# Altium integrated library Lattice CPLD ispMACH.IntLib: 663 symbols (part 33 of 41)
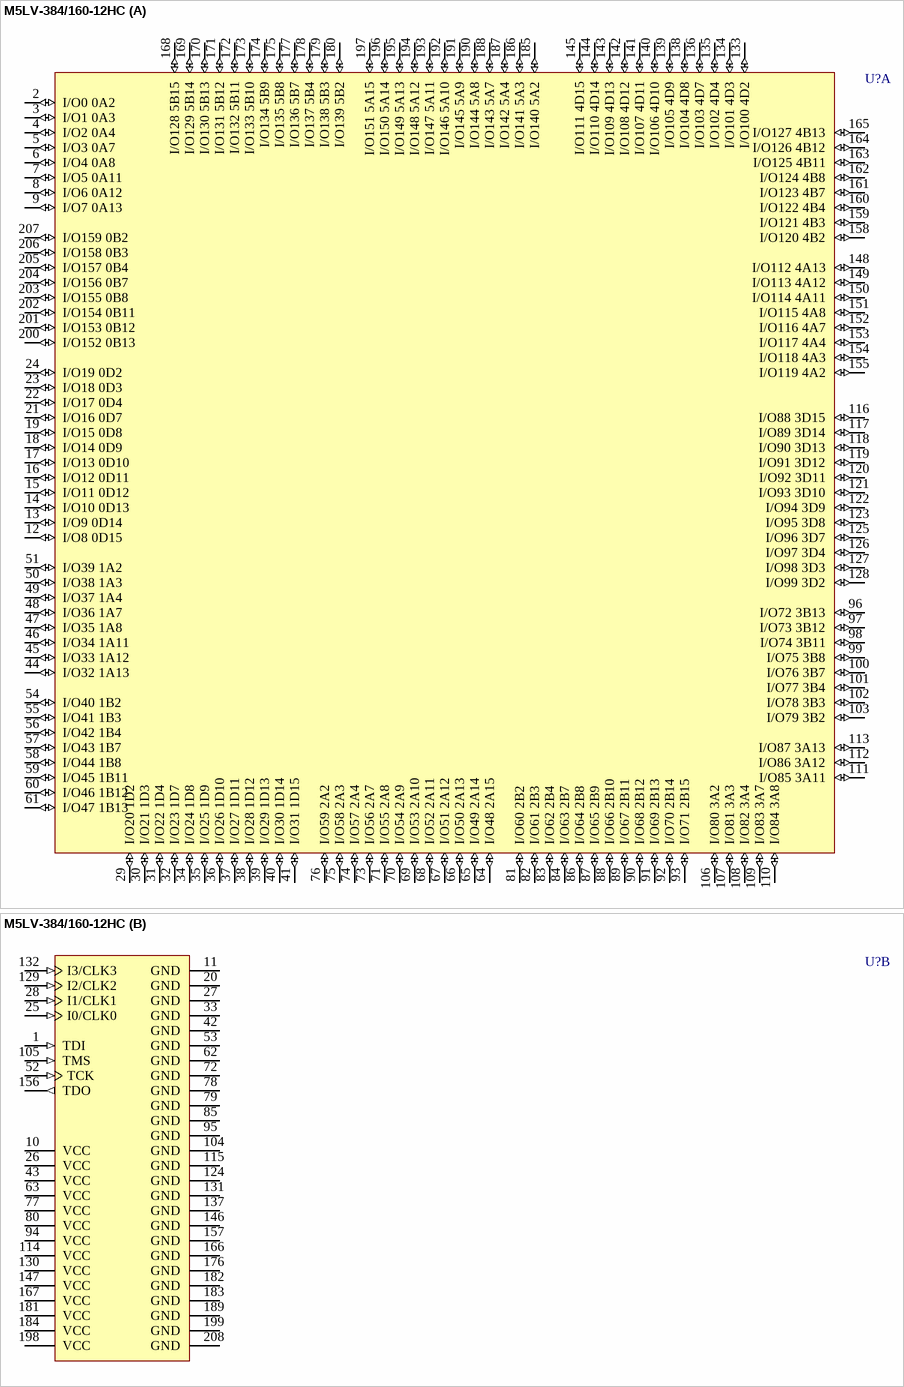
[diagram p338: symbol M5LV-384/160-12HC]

## M5LV-384/160-12HC
designator U?
High-Density and High-I/O Complex PLD
footprint MQFP208_N (Shrink QFP, 208-Leads, Body 27.7x27.7mm, Pitch 0.5mm, IPC Medium Density)
footprint MQFP208_L (Shrink QFP, 208-Leads, Body 27.7x27.7mm, Pitch 0.5mm, IPC High Density)
footprint MQFP208_M (Shrink QFP, 208-Leads, Body 27.7x27.7mm, Pitch 0.5mm, IPC Low Density)
3D model M5LV-MQFP208 (208-Pin Shrink Quad Flat Pack 0.5 mm Pitch)
part A pins: 2 I/O0 0A2 (io), 3 I/O1 0A3 (io), 4 I/O2 0A4 (io), 5 I/O3 0A7 (io), 6 I/O4 0A8 (io), 7 I/O5 0A11 (io), 8 I/O6 0A12 (io), 9 I/O7 0A13 (io), 12 I/O8 0D15 (io), 13 I/O9 0D14 (io), 14 I/O10 0D13 (io), 15 I/O11 0D12 (io), 16 I/O12 0D11 (io), 17 I/O13 0D10 (io), 18 I/O14 0D9 (io), 19 I/O15 0D8 (io), 21 I/O16 0D7 (io), 22 I/O17 0D4 (io), 23 I/O18 0D3 (io), 24 I/O19 0D2 (io), 29 I/O20 1D2 (io), 30 I/O21 1D3 (io), 31 I/O22 1D4 (io), 32 I/O23 1D7 (io), 34 I/O24 1D8 (io), 35 I/O25 1D9 (io), 36 I/O26 1D10 (io), 37 I/O27 1D11 (io), 38 I/O28 1D12 (io), 39 I/O29 1D13 (io), 40 I/O30 1D14 (io), 41 I/O31 1D15 (io), 44 I/O32 1A13 (io), 45 I/O33 1A12 (io), 46 I/O34 1A11 (io), 47 I/O35 1A8 (io), 48 I/O36 1A7 (io), 49 I/O37 1A4 (io), 50 I/O38 1A3 (io), 51 I/O39 1A2 (io), 54 I/O40 1B2 (io), 55 I/O41 1B3 (io), 56 I/O42 1B4 (io), 57 I/O43 1B7 (io), 58 I/O44 1B8 (io), 59 I/O45 1B11 (io), 60 I/O46 1B12 (io), 61 I/O47 1B13 (io), 64 I/O48 2A15 (io), 65 I/O49 2A14 (io), 66 I/O50 2A13 (io), 67 I/O51 2A12 (io), 68 I/O52 2A11 (io), 69 I/O53 2A10 (io), 70 I/O54 2A9 (io), 71 I/O55 2A8 (io), 73 I/O56 2A7 (io), 74 I/O57 2A4 (io), 75 I/O58 2A3 (io), 76 I/O59 2A2 (io), 81 I/O60 2B2 (io), 82 I/O61 2B3 (io), 83 I/O62 2B4 (io), 84 I/O63 2B7 (io), 86 I/O64 2B8 (io), 87 I/O65 2B9 (io), 88 I/O66 2B10 (io), 89 I/O67 2B11 (io), 90 I/O68 2B12 (io), 91 I/O69 2B13 (io), 92 I/O70 2B14 (io), 93 I/O71 2B15 (io), 96 I/O72 3B13 (io), 97 I/O73 3B12 (io), 98 I/O74 3B11 (io), 99 I/O75 3B8 (io), 100 I/O76 3B7 (io), 101 I/O77 3B4 (io), 102 I/O78 3B3 (io), 103 I/O79 3B2 (io), 106 I/O80 3A2 (io), 107 I/O81 3A3 (io), 108 I/O82 3A4 (io), 109 I/O83 3A7 (io), 110 I/O84 3A8 (io), 111 I/O85 3A11 (io), 112 I/O86 3A12 (io), 113 I/O87 3A13 (io), 116 I/O88 3D15 (io), 117 I/O89 3D14 (io), 118 I/O90 3D13 (io), 119 I/O91 3D12 (io), 120 I/O92 3D11 (io), 121 I/O93 3D10 (io), 122 I/O94 3D9 (io), 123 I/O95 3D8 (io), 125 I/O96 3D7 (io), 126 I/O97 3D4 (io), 127 I/O98 3D3 (io), 128 I/O99 3D2 (io), 133 I/O100 4D2 (io), 134 I/O101 4D3 (io), 135 I/O102 4D4 (io), 136 I/O103 4D7 (io), 138 I/O104 4D8 (io), 139 I/O105 4D9 (io), 140 I/O106 4D10 (io), 141 I/O107 4D11 (io), 142 I/O108 4D12 (io), 143 I/O109 4D13 (io), 144 I/O110 4D14 (io), 145 I/O111 4D15 (io), 148 I/O112 4A13 (io), 149 I/O113 4A12 (io), 150 I/O114 4A11 (io), 151 I/O115 4A8 (io), 152 I/O116 4A7 (io), 153 I/O117 4A4 (io), 154 I/O118 4A3 (io), 155 I/O119 4A2 (io), 158 I/O120 4B2 (io), 159 I/O121 4B3 (io), 160 I/O122 4B4 (io), 161 I/O123 4B7 (io), 162 I/O124 4B8 (io), 163 I/O125 4B11 (io), 164 I/O126 4B12 (io), 165 I/O127 4B13 (io), 168 I/O128 5B15 (io), 169 I/O129 5B14 (io), 170 I/O130 5B13 (io), 171 I/O131 5B12 (io), 172 I/O132 5B11 (io), 173 I/O133 5B10 (io), 174 I/O134 5B9 (io), 175 I/O135 5B8 (io), 177 I/O136 5B7 (io), 178 I/O137 5B4 (io), 179 I/O138 5B3 (io), 180 I/O139 5B2 (io), 185 I/O140 5A2 (io), 186 I/O141 5A3 (io), 187 I/O142 5A4 (io), 188 I/O143 5A7 (io), 190 I/O144 5A8 (io), 191 I/O145 5A9 (io), 192 I/O146 5A10 (io), 193 I/O147 5A11 (io), 194 I/O148 5A12 (io), 195 I/O149 5A13 (io), 196 I/O150 5A14 (io), 197 I/O151 5A15 (io), 200 I/O152 0B13 (io), 201 I/O153 0B12 (io), 202 I/O154 0B11 (io), 203 I/O155 0B8 (io), 204 I/O156 0B7 (io), 205 I/O157 0B4 (io), 206 I/O158 0B3 (io), 207 I/O159 0B2 (io)
part B pins: 1 TDI (in), 10 VCC (power), 11 GND (power), 20 GND (power), 25 I0/CLK0 (in), 26 VCC (power), 27 GND (power), 28 I1/CLK1 (in), 33 GND (power), 42 GND (power), 43 VCC (power), 52 TCK (in), 53 GND (power), 62 GND (power), 63 VCC (power), 72 GND (power), 77 VCC (power), 78 GND (power), 79 GND (power), 80 VCC (power), 85 GND (power), 94 VCC (power), 95 GND (power), 104 GND (power), 105 TMS (in), 114 VCC (power), 115 GND (power), 124 GND (power), 129 I2/CLK2 (in), 130 VCC (power), 131 GND (power), 132 I3/CLK3 (in), 137 GND (power), 146 GND (power), 147 VCC (power), 156 TDO (out), 157 GND (power), 166 GND (power), 167 VCC (power), 176 GND (power), 181 VCC (power), 182 GND (power), 183 GND (power), 184 VCC (power), 189 GND (power), 198 VCC (power), 199 GND (power), 208 GND (power)

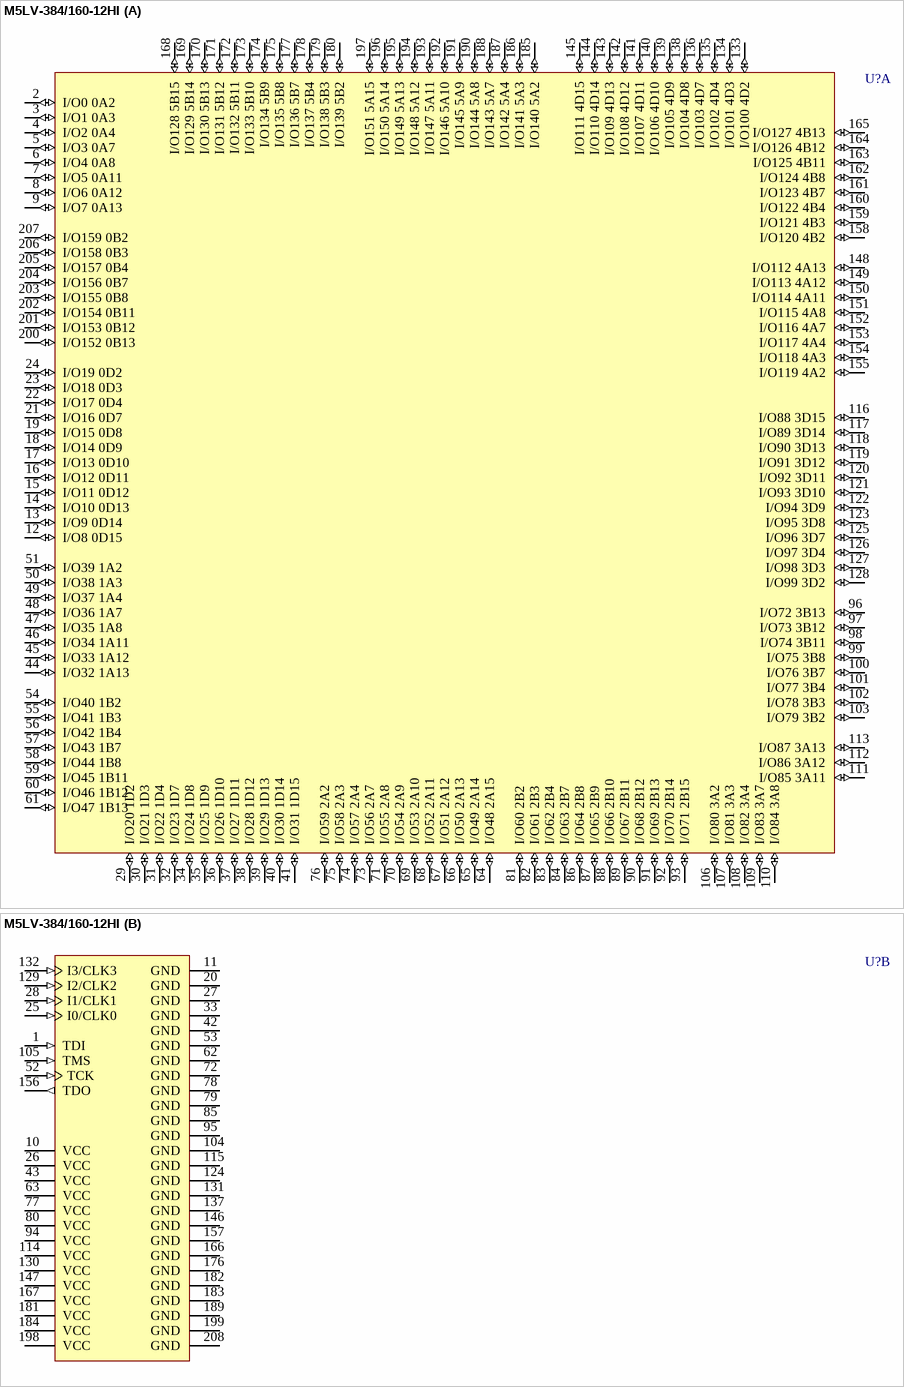
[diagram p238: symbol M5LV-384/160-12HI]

## M5LV-384/160-12HI
designator U?
High-Density and High-I/O Complex PLD
footprint MQFP208_N (Shrink QFP, 208-Leads, Body 27.7x27.7mm, Pitch 0.5mm, IPC Medium Density)
footprint MQFP208_L (Shrink QFP, 208-Leads, Body 27.7x27.7mm, Pitch 0.5mm, IPC High Density)
footprint MQFP208_M (Shrink QFP, 208-Leads, Body 27.7x27.7mm, Pitch 0.5mm, IPC Low Density)
3D model M5LV-MQFP208 (208-Pin Shrink Quad Flat Pack 0.5 mm Pitch)
part A pins: 2 I/O0 0A2 (io), 3 I/O1 0A3 (io), 4 I/O2 0A4 (io), 5 I/O3 0A7 (io), 6 I/O4 0A8 (io), 7 I/O5 0A11 (io), 8 I/O6 0A12 (io), 9 I/O7 0A13 (io), 12 I/O8 0D15 (io), 13 I/O9 0D14 (io), 14 I/O10 0D13 (io), 15 I/O11 0D12 (io), 16 I/O12 0D11 (io), 17 I/O13 0D10 (io), 18 I/O14 0D9 (io), 19 I/O15 0D8 (io), 21 I/O16 0D7 (io), 22 I/O17 0D4 (io), 23 I/O18 0D3 (io), 24 I/O19 0D2 (io), 29 I/O20 1D2 (io), 30 I/O21 1D3 (io), 31 I/O22 1D4 (io), 32 I/O23 1D7 (io), 34 I/O24 1D8 (io), 35 I/O25 1D9 (io), 36 I/O26 1D10 (io), 37 I/O27 1D11 (io), 38 I/O28 1D12 (io), 39 I/O29 1D13 (io), 40 I/O30 1D14 (io), 41 I/O31 1D15 (io), 44 I/O32 1A13 (io), 45 I/O33 1A12 (io), 46 I/O34 1A11 (io), 47 I/O35 1A8 (io), 48 I/O36 1A7 (io), 49 I/O37 1A4 (io), 50 I/O38 1A3 (io), 51 I/O39 1A2 (io), 54 I/O40 1B2 (io), 55 I/O41 1B3 (io), 56 I/O42 1B4 (io), 57 I/O43 1B7 (io), 58 I/O44 1B8 (io), 59 I/O45 1B11 (io), 60 I/O46 1B12 (io), 61 I/O47 1B13 (io), 64 I/O48 2A15 (io), 65 I/O49 2A14 (io), 66 I/O50 2A13 (io), 67 I/O51 2A12 (io), 68 I/O52 2A11 (io), 69 I/O53 2A10 (io), 70 I/O54 2A9 (io), 71 I/O55 2A8 (io), 73 I/O56 2A7 (io), 74 I/O57 2A4 (io), 75 I/O58 2A3 (io), 76 I/O59 2A2 (io), 81 I/O60 2B2 (io), 82 I/O61 2B3 (io), 83 I/O62 2B4 (io), 84 I/O63 2B7 (io), 86 I/O64 2B8 (io), 87 I/O65 2B9 (io), 88 I/O66 2B10 (io), 89 I/O67 2B11 (io), 90 I/O68 2B12 (io), 91 I/O69 2B13 (io), 92 I/O70 2B14 (io), 93 I/O71 2B15 (io), 96 I/O72 3B13 (io), 97 I/O73 3B12 (io), 98 I/O74 3B11 (io), 99 I/O75 3B8 (io), 100 I/O76 3B7 (io), 101 I/O77 3B4 (io), 102 I/O78 3B3 (io), 103 I/O79 3B2 (io), 106 I/O80 3A2 (io), 107 I/O81 3A3 (io), 108 I/O82 3A4 (io), 109 I/O83 3A7 (io), 110 I/O84 3A8 (io), 111 I/O85 3A11 (io), 112 I/O86 3A12 (io), 113 I/O87 3A13 (io), 116 I/O88 3D15 (io), 117 I/O89 3D14 (io), 118 I/O90 3D13 (io), 119 I/O91 3D12 (io), 120 I/O92 3D11 (io), 121 I/O93 3D10 (io), 122 I/O94 3D9 (io), 123 I/O95 3D8 (io), 125 I/O96 3D7 (io), 126 I/O97 3D4 (io), 127 I/O98 3D3 (io), 128 I/O99 3D2 (io), 133 I/O100 4D2 (io), 134 I/O101 4D3 (io), 135 I/O102 4D4 (io), 136 I/O103 4D7 (io), 138 I/O104 4D8 (io), 139 I/O105 4D9 (io), 140 I/O106 4D10 (io), 141 I/O107 4D11 (io), 142 I/O108 4D12 (io), 143 I/O109 4D13 (io), 144 I/O110 4D14 (io), 145 I/O111 4D15 (io), 148 I/O112 4A13 (io), 149 I/O113 4A12 (io), 150 I/O114 4A11 (io), 151 I/O115 4A8 (io), 152 I/O116 4A7 (io), 153 I/O117 4A4 (io), 154 I/O118 4A3 (io), 155 I/O119 4A2 (io), 158 I/O120 4B2 (io), 159 I/O121 4B3 (io), 160 I/O122 4B4 (io), 161 I/O123 4B7 (io), 162 I/O124 4B8 (io), 163 I/O125 4B11 (io), 164 I/O126 4B12 (io), 165 I/O127 4B13 (io), 168 I/O128 5B15 (io), 169 I/O129 5B14 (io), 170 I/O130 5B13 (io), 171 I/O131 5B12 (io), 172 I/O132 5B11 (io), 173 I/O133 5B10 (io), 174 I/O134 5B9 (io), 175 I/O135 5B8 (io), 177 I/O136 5B7 (io), 178 I/O137 5B4 (io), 179 I/O138 5B3 (io), 180 I/O139 5B2 (io), 185 I/O140 5A2 (io), 186 I/O141 5A3 (io), 187 I/O142 5A4 (io), 188 I/O143 5A7 (io), 190 I/O144 5A8 (io), 191 I/O145 5A9 (io), 192 I/O146 5A10 (io), 193 I/O147 5A11 (io), 194 I/O148 5A12 (io), 195 I/O149 5A13 (io), 196 I/O150 5A14 (io), 197 I/O151 5A15 (io), 200 I/O152 0B13 (io), 201 I/O153 0B12 (io), 202 I/O154 0B11 (io), 203 I/O155 0B8 (io), 204 I/O156 0B7 (io), 205 I/O157 0B4 (io), 206 I/O158 0B3 (io), 207 I/O159 0B2 (io)
part B pins: 1 TDI (in), 10 VCC (power), 11 GND (power), 20 GND (power), 25 I0/CLK0 (in), 26 VCC (power), 27 GND (power), 28 I1/CLK1 (in), 33 GND (power), 42 GND (power), 43 VCC (power), 52 TCK (in), 53 GND (power), 62 GND (power), 63 VCC (power), 72 GND (power), 77 VCC (power), 78 GND (power), 79 GND (power), 80 VCC (power), 85 GND (power), 94 VCC (power), 95 GND (power), 104 GND (power), 105 TMS (in), 114 VCC (power), 115 GND (power), 124 GND (power), 129 I2/CLK2 (in), 130 VCC (power), 131 GND (power), 132 I3/CLK3 (in), 137 GND (power), 146 GND (power), 147 VCC (power), 156 TDO (out), 157 GND (power), 166 GND (power), 167 VCC (power), 176 GND (power), 181 VCC (power), 182 GND (power), 183 GND (power), 184 VCC (power), 189 GND (power), 198 VCC (power), 199 GND (power), 208 GND (power)

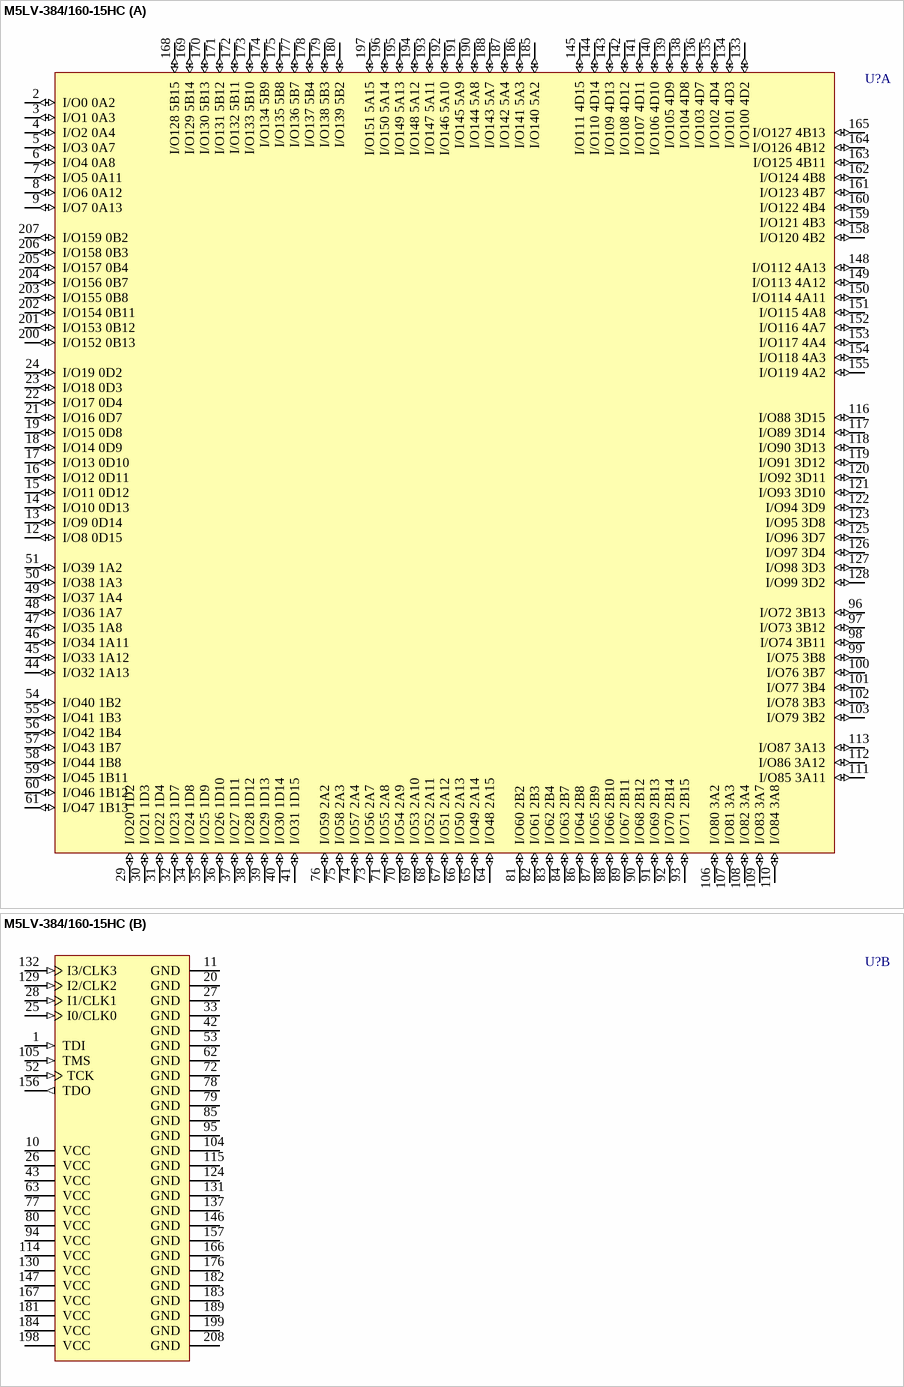
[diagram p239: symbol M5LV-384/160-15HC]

## M5LV-384/160-15HC
designator U?
High-Density and High-I/O Complex PLD
footprint MQFP208_N (Shrink QFP, 208-Leads, Body 27.7x27.7mm, Pitch 0.5mm, IPC Medium Density)
footprint MQFP208_L (Shrink QFP, 208-Leads, Body 27.7x27.7mm, Pitch 0.5mm, IPC High Density)
footprint MQFP208_M (Shrink QFP, 208-Leads, Body 27.7x27.7mm, Pitch 0.5mm, IPC Low Density)
3D model M5LV-MQFP208 (208-Pin Shrink Quad Flat Pack 0.5 mm Pitch)
part A pins: 2 I/O0 0A2 (io), 3 I/O1 0A3 (io), 4 I/O2 0A4 (io), 5 I/O3 0A7 (io), 6 I/O4 0A8 (io), 7 I/O5 0A11 (io), 8 I/O6 0A12 (io), 9 I/O7 0A13 (io), 12 I/O8 0D15 (io), 13 I/O9 0D14 (io), 14 I/O10 0D13 (io), 15 I/O11 0D12 (io), 16 I/O12 0D11 (io), 17 I/O13 0D10 (io), 18 I/O14 0D9 (io), 19 I/O15 0D8 (io), 21 I/O16 0D7 (io), 22 I/O17 0D4 (io), 23 I/O18 0D3 (io), 24 I/O19 0D2 (io), 29 I/O20 1D2 (io), 30 I/O21 1D3 (io), 31 I/O22 1D4 (io), 32 I/O23 1D7 (io), 34 I/O24 1D8 (io), 35 I/O25 1D9 (io), 36 I/O26 1D10 (io), 37 I/O27 1D11 (io), 38 I/O28 1D12 (io), 39 I/O29 1D13 (io), 40 I/O30 1D14 (io), 41 I/O31 1D15 (io), 44 I/O32 1A13 (io), 45 I/O33 1A12 (io), 46 I/O34 1A11 (io), 47 I/O35 1A8 (io), 48 I/O36 1A7 (io), 49 I/O37 1A4 (io), 50 I/O38 1A3 (io), 51 I/O39 1A2 (io), 54 I/O40 1B2 (io), 55 I/O41 1B3 (io), 56 I/O42 1B4 (io), 57 I/O43 1B7 (io), 58 I/O44 1B8 (io), 59 I/O45 1B11 (io), 60 I/O46 1B12 (io), 61 I/O47 1B13 (io), 64 I/O48 2A15 (io), 65 I/O49 2A14 (io), 66 I/O50 2A13 (io), 67 I/O51 2A12 (io), 68 I/O52 2A11 (io), 69 I/O53 2A10 (io), 70 I/O54 2A9 (io), 71 I/O55 2A8 (io), 73 I/O56 2A7 (io), 74 I/O57 2A4 (io), 75 I/O58 2A3 (io), 76 I/O59 2A2 (io), 81 I/O60 2B2 (io), 82 I/O61 2B3 (io), 83 I/O62 2B4 (io), 84 I/O63 2B7 (io), 86 I/O64 2B8 (io), 87 I/O65 2B9 (io), 88 I/O66 2B10 (io), 89 I/O67 2B11 (io), 90 I/O68 2B12 (io), 91 I/O69 2B13 (io), 92 I/O70 2B14 (io), 93 I/O71 2B15 (io), 96 I/O72 3B13 (io), 97 I/O73 3B12 (io), 98 I/O74 3B11 (io), 99 I/O75 3B8 (io), 100 I/O76 3B7 (io), 101 I/O77 3B4 (io), 102 I/O78 3B3 (io), 103 I/O79 3B2 (io), 106 I/O80 3A2 (io), 107 I/O81 3A3 (io), 108 I/O82 3A4 (io), 109 I/O83 3A7 (io), 110 I/O84 3A8 (io), 111 I/O85 3A11 (io), 112 I/O86 3A12 (io), 113 I/O87 3A13 (io), 116 I/O88 3D15 (io), 117 I/O89 3D14 (io), 118 I/O90 3D13 (io), 119 I/O91 3D12 (io), 120 I/O92 3D11 (io), 121 I/O93 3D10 (io), 122 I/O94 3D9 (io), 123 I/O95 3D8 (io), 125 I/O96 3D7 (io), 126 I/O97 3D4 (io), 127 I/O98 3D3 (io), 128 I/O99 3D2 (io), 133 I/O100 4D2 (io), 134 I/O101 4D3 (io), 135 I/O102 4D4 (io), 136 I/O103 4D7 (io), 138 I/O104 4D8 (io), 139 I/O105 4D9 (io), 140 I/O106 4D10 (io), 141 I/O107 4D11 (io), 142 I/O108 4D12 (io), 143 I/O109 4D13 (io), 144 I/O110 4D14 (io), 145 I/O111 4D15 (io), 148 I/O112 4A13 (io), 149 I/O113 4A12 (io), 150 I/O114 4A11 (io), 151 I/O115 4A8 (io), 152 I/O116 4A7 (io), 153 I/O117 4A4 (io), 154 I/O118 4A3 (io), 155 I/O119 4A2 (io), 158 I/O120 4B2 (io), 159 I/O121 4B3 (io), 160 I/O122 4B4 (io), 161 I/O123 4B7 (io), 162 I/O124 4B8 (io), 163 I/O125 4B11 (io), 164 I/O126 4B12 (io), 165 I/O127 4B13 (io), 168 I/O128 5B15 (io), 169 I/O129 5B14 (io), 170 I/O130 5B13 (io), 171 I/O131 5B12 (io), 172 I/O132 5B11 (io), 173 I/O133 5B10 (io), 174 I/O134 5B9 (io), 175 I/O135 5B8 (io), 177 I/O136 5B7 (io), 178 I/O137 5B4 (io), 179 I/O138 5B3 (io), 180 I/O139 5B2 (io), 185 I/O140 5A2 (io), 186 I/O141 5A3 (io), 187 I/O142 5A4 (io), 188 I/O143 5A7 (io), 190 I/O144 5A8 (io), 191 I/O145 5A9 (io), 192 I/O146 5A10 (io), 193 I/O147 5A11 (io), 194 I/O148 5A12 (io), 195 I/O149 5A13 (io), 196 I/O150 5A14 (io), 197 I/O151 5A15 (io), 200 I/O152 0B13 (io), 201 I/O153 0B12 (io), 202 I/O154 0B11 (io), 203 I/O155 0B8 (io), 204 I/O156 0B7 (io), 205 I/O157 0B4 (io), 206 I/O158 0B3 (io), 207 I/O159 0B2 (io)
part B pins: 1 TDI (in), 10 VCC (power), 11 GND (power), 20 GND (power), 25 I0/CLK0 (in), 26 VCC (power), 27 GND (power), 28 I1/CLK1 (in), 33 GND (power), 42 GND (power), 43 VCC (power), 52 TCK (in), 53 GND (power), 62 GND (power), 63 VCC (power), 72 GND (power), 77 VCC (power), 78 GND (power), 79 GND (power), 80 VCC (power), 85 GND (power), 94 VCC (power), 95 GND (power), 104 GND (power), 105 TMS (in), 114 VCC (power), 115 GND (power), 124 GND (power), 129 I2/CLK2 (in), 130 VCC (power), 131 GND (power), 132 I3/CLK3 (in), 137 GND (power), 146 GND (power), 147 VCC (power), 156 TDO (out), 157 GND (power), 166 GND (power), 167 VCC (power), 176 GND (power), 181 VCC (power), 182 GND (power), 183 GND (power), 184 VCC (power), 189 GND (power), 198 VCC (power), 199 GND (power), 208 GND (power)

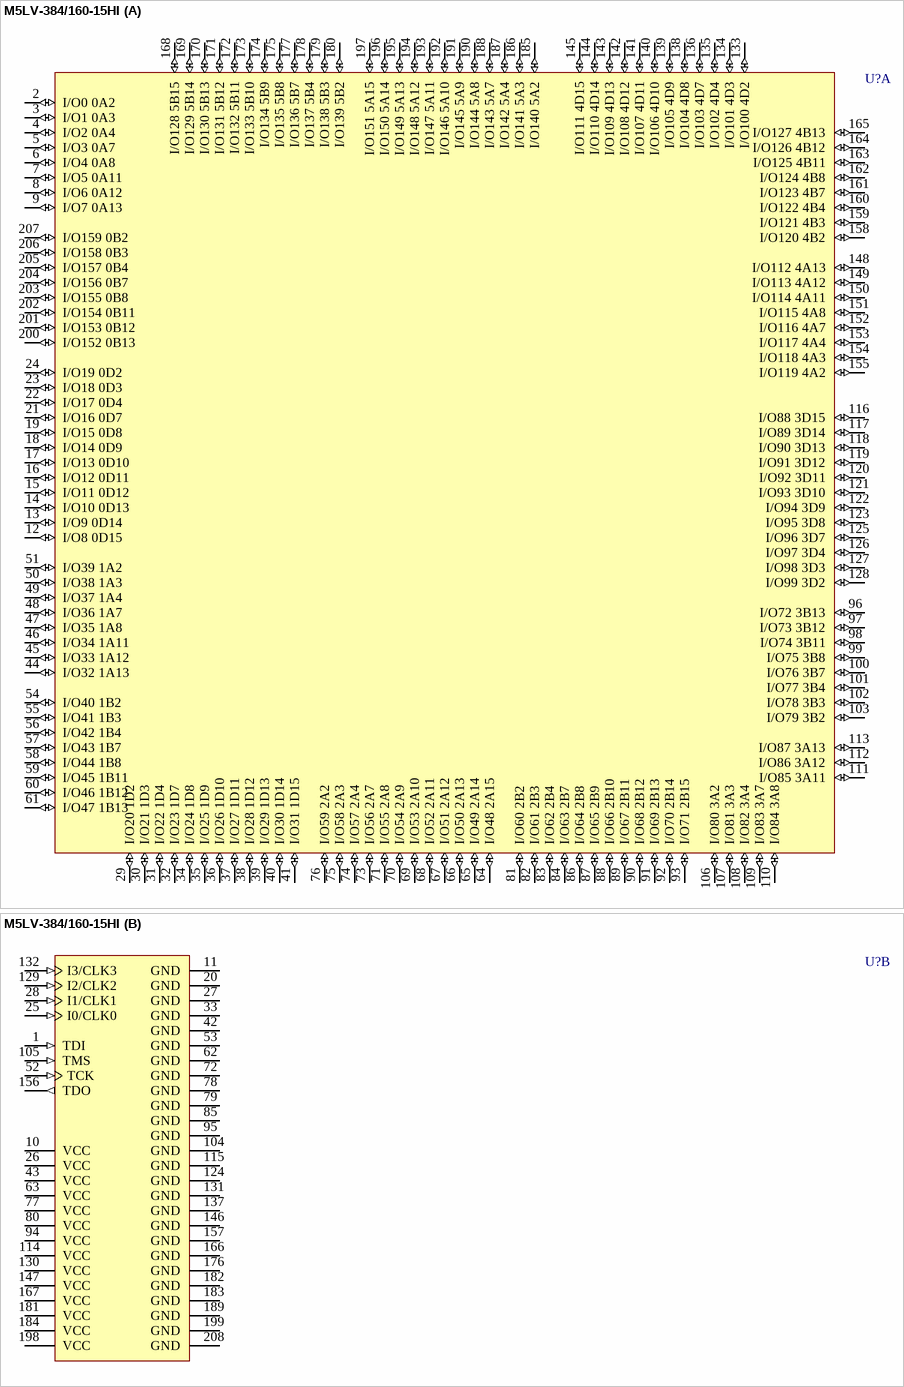
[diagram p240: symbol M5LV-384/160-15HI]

## M5LV-384/160-15HI
designator U?
High-Density and High-I/O Complex PLD
footprint MQFP208_N (Shrink QFP, 208-Leads, Body 27.7x27.7mm, Pitch 0.5mm, IPC Medium Density)
footprint MQFP208_L (Shrink QFP, 208-Leads, Body 27.7x27.7mm, Pitch 0.5mm, IPC High Density)
footprint MQFP208_M (Shrink QFP, 208-Leads, Body 27.7x27.7mm, Pitch 0.5mm, IPC Low Density)
3D model M5LV-MQFP208 (208-Pin Shrink Quad Flat Pack 0.5 mm Pitch)
part A pins: 2 I/O0 0A2 (io), 3 I/O1 0A3 (io), 4 I/O2 0A4 (io), 5 I/O3 0A7 (io), 6 I/O4 0A8 (io), 7 I/O5 0A11 (io), 8 I/O6 0A12 (io), 9 I/O7 0A13 (io), 12 I/O8 0D15 (io), 13 I/O9 0D14 (io), 14 I/O10 0D13 (io), 15 I/O11 0D12 (io), 16 I/O12 0D11 (io), 17 I/O13 0D10 (io), 18 I/O14 0D9 (io), 19 I/O15 0D8 (io), 21 I/O16 0D7 (io), 22 I/O17 0D4 (io), 23 I/O18 0D3 (io), 24 I/O19 0D2 (io), 29 I/O20 1D2 (io), 30 I/O21 1D3 (io), 31 I/O22 1D4 (io), 32 I/O23 1D7 (io), 34 I/O24 1D8 (io), 35 I/O25 1D9 (io), 36 I/O26 1D10 (io), 37 I/O27 1D11 (io), 38 I/O28 1D12 (io), 39 I/O29 1D13 (io), 40 I/O30 1D14 (io), 41 I/O31 1D15 (io), 44 I/O32 1A13 (io), 45 I/O33 1A12 (io), 46 I/O34 1A11 (io), 47 I/O35 1A8 (io), 48 I/O36 1A7 (io), 49 I/O37 1A4 (io), 50 I/O38 1A3 (io), 51 I/O39 1A2 (io), 54 I/O40 1B2 (io), 55 I/O41 1B3 (io), 56 I/O42 1B4 (io), 57 I/O43 1B7 (io), 58 I/O44 1B8 (io), 59 I/O45 1B11 (io), 60 I/O46 1B12 (io), 61 I/O47 1B13 (io), 64 I/O48 2A15 (io), 65 I/O49 2A14 (io), 66 I/O50 2A13 (io), 67 I/O51 2A12 (io), 68 I/O52 2A11 (io), 69 I/O53 2A10 (io), 70 I/O54 2A9 (io), 71 I/O55 2A8 (io), 73 I/O56 2A7 (io), 74 I/O57 2A4 (io), 75 I/O58 2A3 (io), 76 I/O59 2A2 (io), 81 I/O60 2B2 (io), 82 I/O61 2B3 (io), 83 I/O62 2B4 (io), 84 I/O63 2B7 (io), 86 I/O64 2B8 (io), 87 I/O65 2B9 (io), 88 I/O66 2B10 (io), 89 I/O67 2B11 (io), 90 I/O68 2B12 (io), 91 I/O69 2B13 (io), 92 I/O70 2B14 (io), 93 I/O71 2B15 (io), 96 I/O72 3B13 (io), 97 I/O73 3B12 (io), 98 I/O74 3B11 (io), 99 I/O75 3B8 (io), 100 I/O76 3B7 (io), 101 I/O77 3B4 (io), 102 I/O78 3B3 (io), 103 I/O79 3B2 (io), 106 I/O80 3A2 (io), 107 I/O81 3A3 (io), 108 I/O82 3A4 (io), 109 I/O83 3A7 (io), 110 I/O84 3A8 (io), 111 I/O85 3A11 (io), 112 I/O86 3A12 (io), 113 I/O87 3A13 (io), 116 I/O88 3D15 (io), 117 I/O89 3D14 (io), 118 I/O90 3D13 (io), 119 I/O91 3D12 (io), 120 I/O92 3D11 (io), 121 I/O93 3D10 (io), 122 I/O94 3D9 (io), 123 I/O95 3D8 (io), 125 I/O96 3D7 (io), 126 I/O97 3D4 (io), 127 I/O98 3D3 (io), 128 I/O99 3D2 (io), 133 I/O100 4D2 (io), 134 I/O101 4D3 (io), 135 I/O102 4D4 (io), 136 I/O103 4D7 (io), 138 I/O104 4D8 (io), 139 I/O105 4D9 (io), 140 I/O106 4D10 (io), 141 I/O107 4D11 (io), 142 I/O108 4D12 (io), 143 I/O109 4D13 (io), 144 I/O110 4D14 (io), 145 I/O111 4D15 (io), 148 I/O112 4A13 (io), 149 I/O113 4A12 (io), 150 I/O114 4A11 (io), 151 I/O115 4A8 (io), 152 I/O116 4A7 (io), 153 I/O117 4A4 (io), 154 I/O118 4A3 (io), 155 I/O119 4A2 (io), 158 I/O120 4B2 (io), 159 I/O121 4B3 (io), 160 I/O122 4B4 (io), 161 I/O123 4B7 (io), 162 I/O124 4B8 (io), 163 I/O125 4B11 (io), 164 I/O126 4B12 (io), 165 I/O127 4B13 (io), 168 I/O128 5B15 (io), 169 I/O129 5B14 (io), 170 I/O130 5B13 (io), 171 I/O131 5B12 (io), 172 I/O132 5B11 (io), 173 I/O133 5B10 (io), 174 I/O134 5B9 (io), 175 I/O135 5B8 (io), 177 I/O136 5B7 (io), 178 I/O137 5B4 (io), 179 I/O138 5B3 (io), 180 I/O139 5B2 (io), 185 I/O140 5A2 (io), 186 I/O141 5A3 (io), 187 I/O142 5A4 (io), 188 I/O143 5A7 (io), 190 I/O144 5A8 (io), 191 I/O145 5A9 (io), 192 I/O146 5A10 (io), 193 I/O147 5A11 (io), 194 I/O148 5A12 (io), 195 I/O149 5A13 (io), 196 I/O150 5A14 (io), 197 I/O151 5A15 (io), 200 I/O152 0B13 (io), 201 I/O153 0B12 (io), 202 I/O154 0B11 (io), 203 I/O155 0B8 (io), 204 I/O156 0B7 (io), 205 I/O157 0B4 (io), 206 I/O158 0B3 (io), 207 I/O159 0B2 (io)
part B pins: 1 TDI (in), 10 VCC (power), 11 GND (power), 20 GND (power), 25 I0/CLK0 (in), 26 VCC (power), 27 GND (power), 28 I1/CLK1 (in), 33 GND (power), 42 GND (power), 43 VCC (power), 52 TCK (in), 53 GND (power), 62 GND (power), 63 VCC (power), 72 GND (power), 77 VCC (power), 78 GND (power), 79 GND (power), 80 VCC (power), 85 GND (power), 94 VCC (power), 95 GND (power), 104 GND (power), 105 TMS (in), 114 VCC (power), 115 GND (power), 124 GND (power), 129 I2/CLK2 (in), 130 VCC (power), 131 GND (power), 132 I3/CLK3 (in), 137 GND (power), 146 GND (power), 147 VCC (power), 156 TDO (out), 157 GND (power), 166 GND (power), 167 VCC (power), 176 GND (power), 181 VCC (power), 182 GND (power), 183 GND (power), 184 VCC (power), 189 GND (power), 198 VCC (power), 199 GND (power), 208 GND (power)

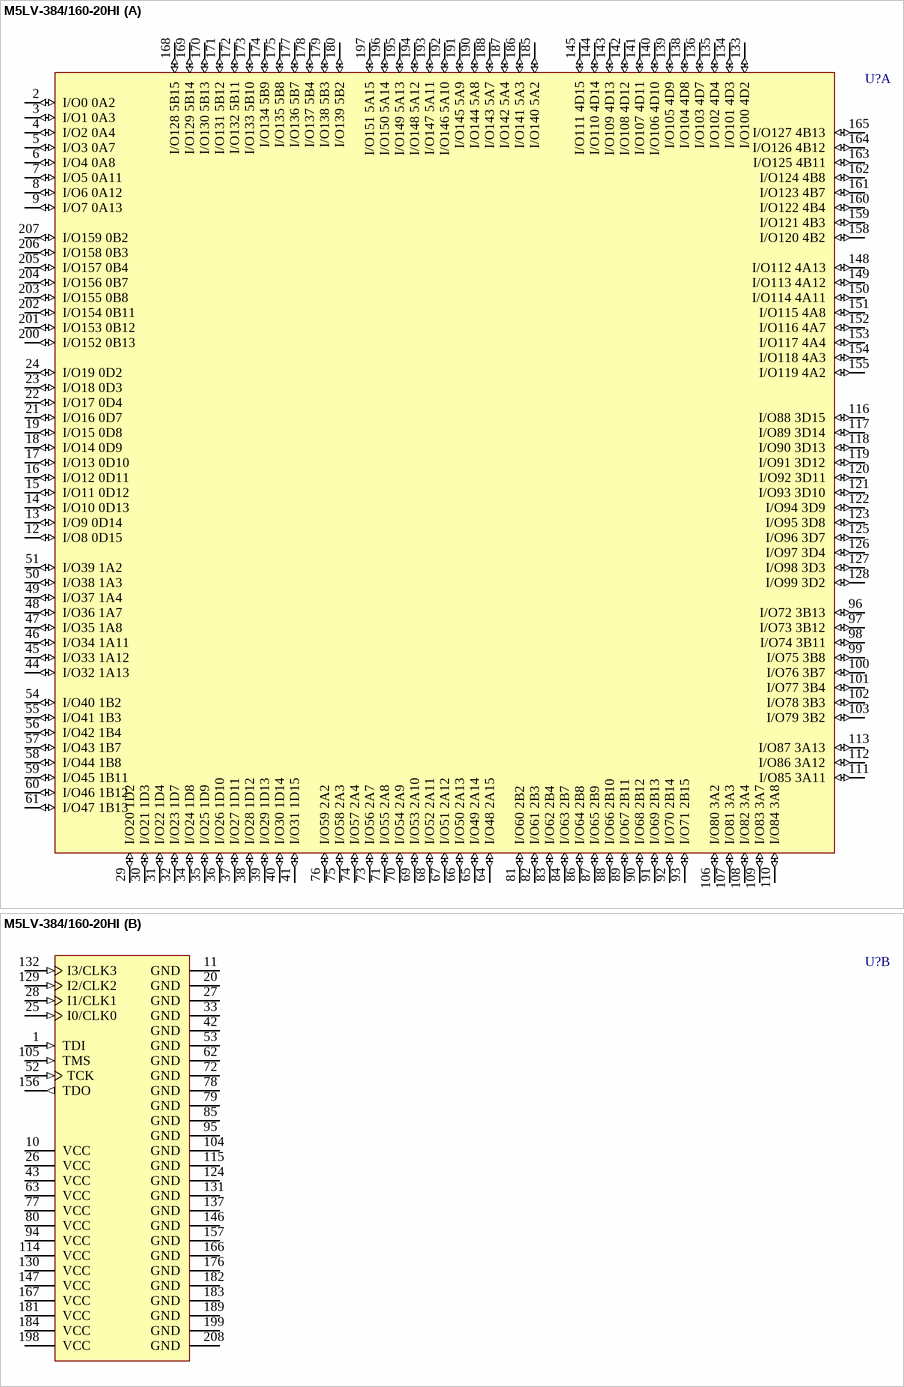
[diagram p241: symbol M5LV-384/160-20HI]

## M5LV-384/160-20HI
designator U?
High-Density and High-I/O Complex PLD
footprint MQFP208_N (Shrink QFP, 208-Leads, Body 27.7x27.7mm, Pitch 0.5mm, IPC Medium Density)
footprint MQFP208_L (Shrink QFP, 208-Leads, Body 27.7x27.7mm, Pitch 0.5mm, IPC High Density)
footprint MQFP208_M (Shrink QFP, 208-Leads, Body 27.7x27.7mm, Pitch 0.5mm, IPC Low Density)
3D model M5LV-MQFP208 (208-Pin Shrink Quad Flat Pack 0.5 mm Pitch)
part A pins: 2 I/O0 0A2 (io), 3 I/O1 0A3 (io), 4 I/O2 0A4 (io), 5 I/O3 0A7 (io), 6 I/O4 0A8 (io), 7 I/O5 0A11 (io), 8 I/O6 0A12 (io), 9 I/O7 0A13 (io), 12 I/O8 0D15 (io), 13 I/O9 0D14 (io), 14 I/O10 0D13 (io), 15 I/O11 0D12 (io), 16 I/O12 0D11 (io), 17 I/O13 0D10 (io), 18 I/O14 0D9 (io), 19 I/O15 0D8 (io), 21 I/O16 0D7 (io), 22 I/O17 0D4 (io), 23 I/O18 0D3 (io), 24 I/O19 0D2 (io), 29 I/O20 1D2 (io), 30 I/O21 1D3 (io), 31 I/O22 1D4 (io), 32 I/O23 1D7 (io), 34 I/O24 1D8 (io), 35 I/O25 1D9 (io), 36 I/O26 1D10 (io), 37 I/O27 1D11 (io), 38 I/O28 1D12 (io), 39 I/O29 1D13 (io), 40 I/O30 1D14 (io), 41 I/O31 1D15 (io), 44 I/O32 1A13 (io), 45 I/O33 1A12 (io), 46 I/O34 1A11 (io), 47 I/O35 1A8 (io), 48 I/O36 1A7 (io), 49 I/O37 1A4 (io), 50 I/O38 1A3 (io), 51 I/O39 1A2 (io), 54 I/O40 1B2 (io), 55 I/O41 1B3 (io), 56 I/O42 1B4 (io), 57 I/O43 1B7 (io), 58 I/O44 1B8 (io), 59 I/O45 1B11 (io), 60 I/O46 1B12 (io), 61 I/O47 1B13 (io), 64 I/O48 2A15 (io), 65 I/O49 2A14 (io), 66 I/O50 2A13 (io), 67 I/O51 2A12 (io), 68 I/O52 2A11 (io), 69 I/O53 2A10 (io), 70 I/O54 2A9 (io), 71 I/O55 2A8 (io), 73 I/O56 2A7 (io), 74 I/O57 2A4 (io), 75 I/O58 2A3 (io), 76 I/O59 2A2 (io), 81 I/O60 2B2 (io), 82 I/O61 2B3 (io), 83 I/O62 2B4 (io), 84 I/O63 2B7 (io), 86 I/O64 2B8 (io), 87 I/O65 2B9 (io), 88 I/O66 2B10 (io), 89 I/O67 2B11 (io), 90 I/O68 2B12 (io), 91 I/O69 2B13 (io), 92 I/O70 2B14 (io), 93 I/O71 2B15 (io), 96 I/O72 3B13 (io), 97 I/O73 3B12 (io), 98 I/O74 3B11 (io), 99 I/O75 3B8 (io), 100 I/O76 3B7 (io), 101 I/O77 3B4 (io), 102 I/O78 3B3 (io), 103 I/O79 3B2 (io), 106 I/O80 3A2 (io), 107 I/O81 3A3 (io), 108 I/O82 3A4 (io), 109 I/O83 3A7 (io), 110 I/O84 3A8 (io), 111 I/O85 3A11 (io), 112 I/O86 3A12 (io), 113 I/O87 3A13 (io), 116 I/O88 3D15 (io), 117 I/O89 3D14 (io), 118 I/O90 3D13 (io), 119 I/O91 3D12 (io), 120 I/O92 3D11 (io), 121 I/O93 3D10 (io), 122 I/O94 3D9 (io), 123 I/O95 3D8 (io), 125 I/O96 3D7 (io), 126 I/O97 3D4 (io), 127 I/O98 3D3 (io), 128 I/O99 3D2 (io), 133 I/O100 4D2 (io), 134 I/O101 4D3 (io), 135 I/O102 4D4 (io), 136 I/O103 4D7 (io), 138 I/O104 4D8 (io), 139 I/O105 4D9 (io), 140 I/O106 4D10 (io), 141 I/O107 4D11 (io), 142 I/O108 4D12 (io), 143 I/O109 4D13 (io), 144 I/O110 4D14 (io), 145 I/O111 4D15 (io), 148 I/O112 4A13 (io), 149 I/O113 4A12 (io), 150 I/O114 4A11 (io), 151 I/O115 4A8 (io), 152 I/O116 4A7 (io), 153 I/O117 4A4 (io), 154 I/O118 4A3 (io), 155 I/O119 4A2 (io), 158 I/O120 4B2 (io), 159 I/O121 4B3 (io), 160 I/O122 4B4 (io), 161 I/O123 4B7 (io), 162 I/O124 4B8 (io), 163 I/O125 4B11 (io), 164 I/O126 4B12 (io), 165 I/O127 4B13 (io), 168 I/O128 5B15 (io), 169 I/O129 5B14 (io), 170 I/O130 5B13 (io), 171 I/O131 5B12 (io), 172 I/O132 5B11 (io), 173 I/O133 5B10 (io), 174 I/O134 5B9 (io), 175 I/O135 5B8 (io), 177 I/O136 5B7 (io), 178 I/O137 5B4 (io), 179 I/O138 5B3 (io), 180 I/O139 5B2 (io), 185 I/O140 5A2 (io), 186 I/O141 5A3 (io), 187 I/O142 5A4 (io), 188 I/O143 5A7 (io), 190 I/O144 5A8 (io), 191 I/O145 5A9 (io), 192 I/O146 5A10 (io), 193 I/O147 5A11 (io), 194 I/O148 5A12 (io), 195 I/O149 5A13 (io), 196 I/O150 5A14 (io), 197 I/O151 5A15 (io), 200 I/O152 0B13 (io), 201 I/O153 0B12 (io), 202 I/O154 0B11 (io), 203 I/O155 0B8 (io), 204 I/O156 0B7 (io), 205 I/O157 0B4 (io), 206 I/O158 0B3 (io), 207 I/O159 0B2 (io)
part B pins: 1 TDI (in), 10 VCC (power), 11 GND (power), 20 GND (power), 25 I0/CLK0 (in), 26 VCC (power), 27 GND (power), 28 I1/CLK1 (in), 33 GND (power), 42 GND (power), 43 VCC (power), 52 TCK (in), 53 GND (power), 62 GND (power), 63 VCC (power), 72 GND (power), 77 VCC (power), 78 GND (power), 79 GND (power), 80 VCC (power), 85 GND (power), 94 VCC (power), 95 GND (power), 104 GND (power), 105 TMS (in), 114 VCC (power), 115 GND (power), 124 GND (power), 129 I2/CLK2 (in), 130 VCC (power), 131 GND (power), 132 I3/CLK3 (in), 137 GND (power), 146 GND (power), 147 VCC (power), 156 TDO (out), 157 GND (power), 166 GND (power), 167 VCC (power), 176 GND (power), 181 VCC (power), 182 GND (power), 183 GND (power), 184 VCC (power), 189 GND (power), 198 VCC (power), 199 GND (power), 208 GND (power)

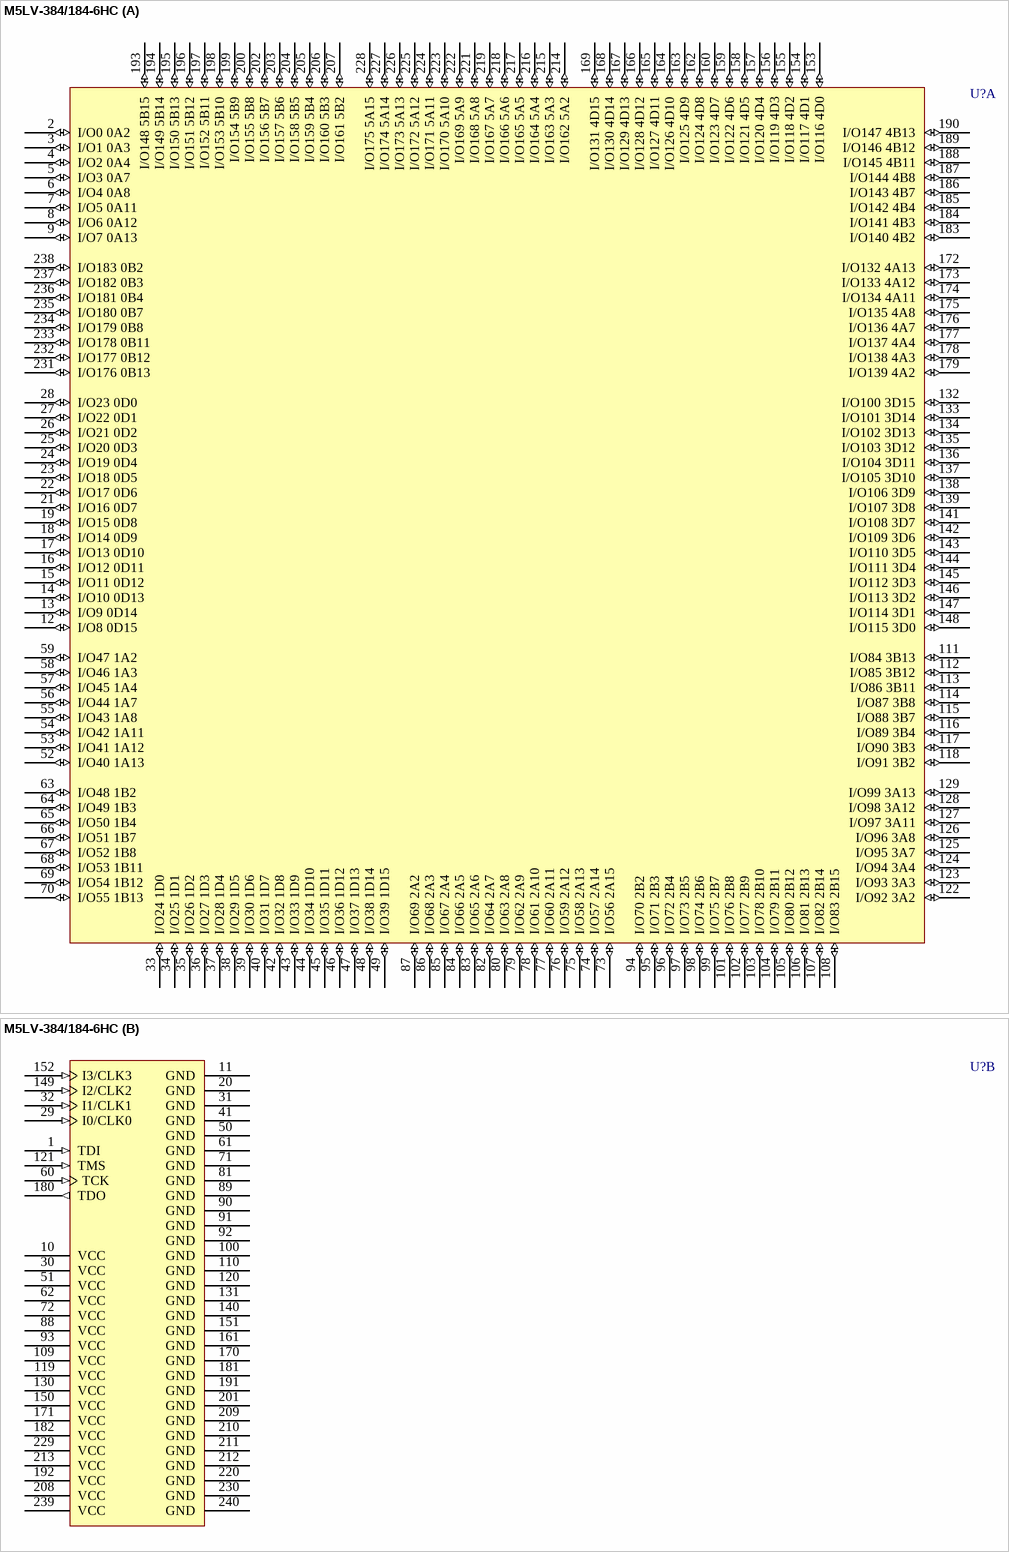
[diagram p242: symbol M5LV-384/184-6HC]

## M5LV-384/184-6HC
designator U?
High-Density and High-I/O Complex PLD
footprint PQFP240_N (Shrink QFP, 240-Leads, Body 32x32mm, Pitch 0.5mm, IPC Medium Density)
footprint PQFP240_L (Shrink QFP, 240-Leads, Body 32x32mm, Pitch 0.5mm, IPC High Density)
footprint PQFP240_M (Shrink QFP, 240-Leads, Body 32x32mm, Pitch 0.5mm, IPC Low Density)
3D model M5LV-PQFP240 (240-Pin Shrink Quad Flat Pack 0.5 mm Pitch)
part A pins: 2 I/O0 0A2 (io), 3 I/O1 0A3 (io), 4 I/O2 0A4 (io), 5 I/O3 0A7 (io), 6 I/O4 0A8 (io), 7 I/O5 0A11 (io), 8 I/O6 0A12 (io), 9 I/O7 0A13 (io), 12 I/O8 0D15 (io), 13 I/O9 0D14 (io), 14 I/O10 0D13 (io), 15 I/O11 0D12 (io), 16 I/O12 0D11 (io), 17 I/O13 0D10 (io), 18 I/O14 0D9 (io), 19 I/O15 0D8 (io), 21 I/O16 0D7 (io), 22 I/O17 0D6 (io), 23 I/O18 0D5 (io), 24 I/O19 0D4 (io), 25 I/O20 0D3 (io), 26 I/O21 0D2 (io), 27 I/O22 0D1 (io), 28 I/O23 0D0 (io), 33 I/O24 1D0 (io), 34 I/O25 1D1 (io), 35 I/O26 1D2 (io), 36 I/O27 1D3 (io), 37 I/O28 1D4 (io), 38 I/O29 1D5 (io), 39 I/O30 1D6 (io), 40 I/O31 1D7 (io), 42 I/O32 1D8 (io), 43 I/O33 1D9 (io), 44 I/O34 1D10 (io), 45 I/O35 1D11 (io), 46 I/O36 1D12 (io), 47 I/O37 1D13 (io), 48 I/O38 1D14 (io), 49 I/O39 1D15 (io), 52 I/O40 1A13 (io), 53 I/O41 1A12 (io), 54 I/O42 1A11 (io), 55 I/O43 1A8 (io), 56 I/O44 1A7 (io), 57 I/O45 1A4 (io), 58 I/O46 1A3 (io), 59 I/O47 1A2 (io), 63 I/O48 1B2 (io), 64 I/O49 1B3 (io), 65 I/O50 1B4 (io), 66 I/O51 1B7 (io), 67 I/O52 1B8 (io), 68 I/O53 1B11 (io), 69 I/O54 1B12 (io), 70 I/O55 1B13 (io), 73 I/O56 2A15 (io), 74 I/O57 2A14 (io), 75 I/O58 2A13 (io), 76 I/O59 2A12 (io), 77 I/O60 2A11 (io), 78 I/O61 2A10 (io), 79 I/O62 2A9 (io), 80 I/O63 2A8 (io), 82 I/O64 2A7 (io), 83 I/O65 2A6 (io), 84 I/O66 2A5 (io), 85 I/O67 2A4 (io), 86 I/O68 2A3 (io), 87 I/O69 2A2 (io), 94 I/O70 2B2 (io), 95 I/O71 2B3 (io), 96 I/O72 2B4 (io), 97 I/O73 2B5 (io), 98 I/O74 2B6 (io), 99 I/O75 2B7 (io), 101 I/O76 2B8 (io), 102 I/O77 2B9 (io), 103 I/O78 2B10 (io), 104 I/O79 2B11 (io), 105 I/O80 2B12 (io), 106 I/O81 2B13 (io), 107 I/O82 2B14 (io), 108 I/O83 2B15 (io), 111 I/O84 3B13 (io), 112 I/O85 3B12 (io), 113 I/O86 3B11 (io), 114 I/O87 3B8 (io), 115 I/O88 3B7 (io), 116 I/O89 3B4 (io), 117 I/O90 3B3 (io), 118 I/O91 3B2 (io), 122 I/O92 3A2 (io), 123 I/O93 3A3 (io), 124 I/O94 3A4 (io), 125 I/O95 3A7 (io), 126 I/O96 3A8 (io), 127 I/O97 3A11 (io), 128 I/O98 3A12 (io), 129 I/O99 3A13 (io), 132 I/O100 3D15 (io), 133 I/O101 3D14 (io), 134 I/O102 3D13 (io), 135 I/O103 3D12 (io), 136 I/O104 3D11 (io), 137 I/O105 3D10 (io), 138 I/O106 3D9 (io), 139 I/O107 3D8 (io), 141 I/O108 3D7 (io), 142 I/O109 3D6 (io), 143 I/O110 3D5 (io), 144 I/O111 3D4 (io), 145 I/O112 3D3 (io), 146 I/O113 3D2 (io), 147 I/O114 3D1 (io), 148 I/O115 3D0 (io), 153 I/O116 4D0 (io), 154 I/O117 4D1 (io), 155 I/O118 4D2 (io), 156 I/O119 4D3 (io), 157 I/O120 4D4 (io), 158 I/O121 4D5 (io), 159 I/O122 4D6 (io), 160 I/O123 4D7 (io), 162 I/O124 4D8 (io), 163 I/O125 4D9 (io), 164 I/O126 4D10 (io), 165 I/O127 4D11 (io), 166 I/O128 4D12 (io), 167 I/O129 4D13 (io), 168 I/O130 4D14 (io), 169 I/O131 4D15 (io), 172 I/O132 4A13 (io), 173 I/O133 4A12 (io), 174 I/O134 4A11 (io), 175 I/O135 4A8 (io), 176 I/O136 4A7 (io), 177 I/O137 4A4 (io), 178 I/O138 4A3 (io), 179 I/O139 4A2 (io), 183 I/O140 4B2 (io), 184 I/O141 4B3 (io), 185 I/O142 4B4 (io), 186 I/O143 4B7 (io), 187 I/O144 4B8 (io), 188 I/O145 4B11 (io), 189 I/O146 4B12 (io), 190 I/O147 4B13 (io), 193 I/O148 5B15 (io), 194 I/O149 5B14 (io), 195 I/O150 5B13 (io), 196 I/O151 5B12 (io), 197 I/O152 5B11 (io), 198 I/O153 5B10 (io), 199 I/O154 5B9 (io), 200 I/O155 5B8 (io), 202 I/O156 5B7 (io), 203 I/O157 5B6 (io), 204 I/O158 5B5 (io), 205 I/O159 5B4 (io), 206 I/O160 5B3 (io), 207 I/O161 5B2 (io), 214 I/O162 5A2 (io), 215 I/O163 5A3 (io), 216 I/O164 5A4 (io), 217 I/O165 5A5 (io), 218 I/O166 5A6 (io), 219 I/O167 5A7 (io), 221 I/O168 5A8 (io), 222 I/O169 5A9 (io), 223 I/O170 5A10 (io), 224 I/O171 5A11 (io), 225 I/O172 5A12 (io), 226 I/O173 5A13 (io), 227 I/O174 5A14 (io), 228 I/O175 5A15 (io), 231 I/O176 0B13 (io), 232 I/O177 0B12 (io), 233 I/O178 0B11 (io), 234 I/O179 0B8 (io), 235 I/O180 0B7 (io), 236 I/O181 0B4 (io), 237 I/O182 0B3 (io), 238 I/O183 0B2 (io)
part B pins: 1 TDI (in), 10 VCC (power), 11 GND (power), 20 GND (power), 29 I0/CLK0 (in), 30 VCC (power), 31 GND (power), 32 I1/CLK1 (in), 41 GND (power), 50 GND (power), 51 VCC (power), 60 TCK (in), 61 GND (power), 62 VCC (power), 71 GND (power), 72 VCC (power), 81 GND (power), 88 VCC (power), 89 GND (power), 90 GND (power), 91 GND (power), 92 GND (power), 93 VCC (power), 100 GND (power), 109 VCC (power), 110 GND (power), 119 VCC (power), 120 GND (power), 121 TMS (in), 130 VCC (power), 131 GND (power), 140 GND (power), 149 I2/CLK2 (in), 150 VCC (power), 151 GND (power), 152 I3/CLK3 (in), 161 GND (power), 170 GND (power), 171 VCC (power), 180 TDO (out), 181 GND (power), 182 VCC (power), 191 GND (power), 192 VCC (power), 201 GND (power), 208 VCC (power), 209 GND (power), 210 GND (power), 211 GND (power), 212 GND (power), 213 VCC (power), 220 GND (power), 229 VCC (power), 230 GND (power), 239 VCC (power), 240 GND (power)

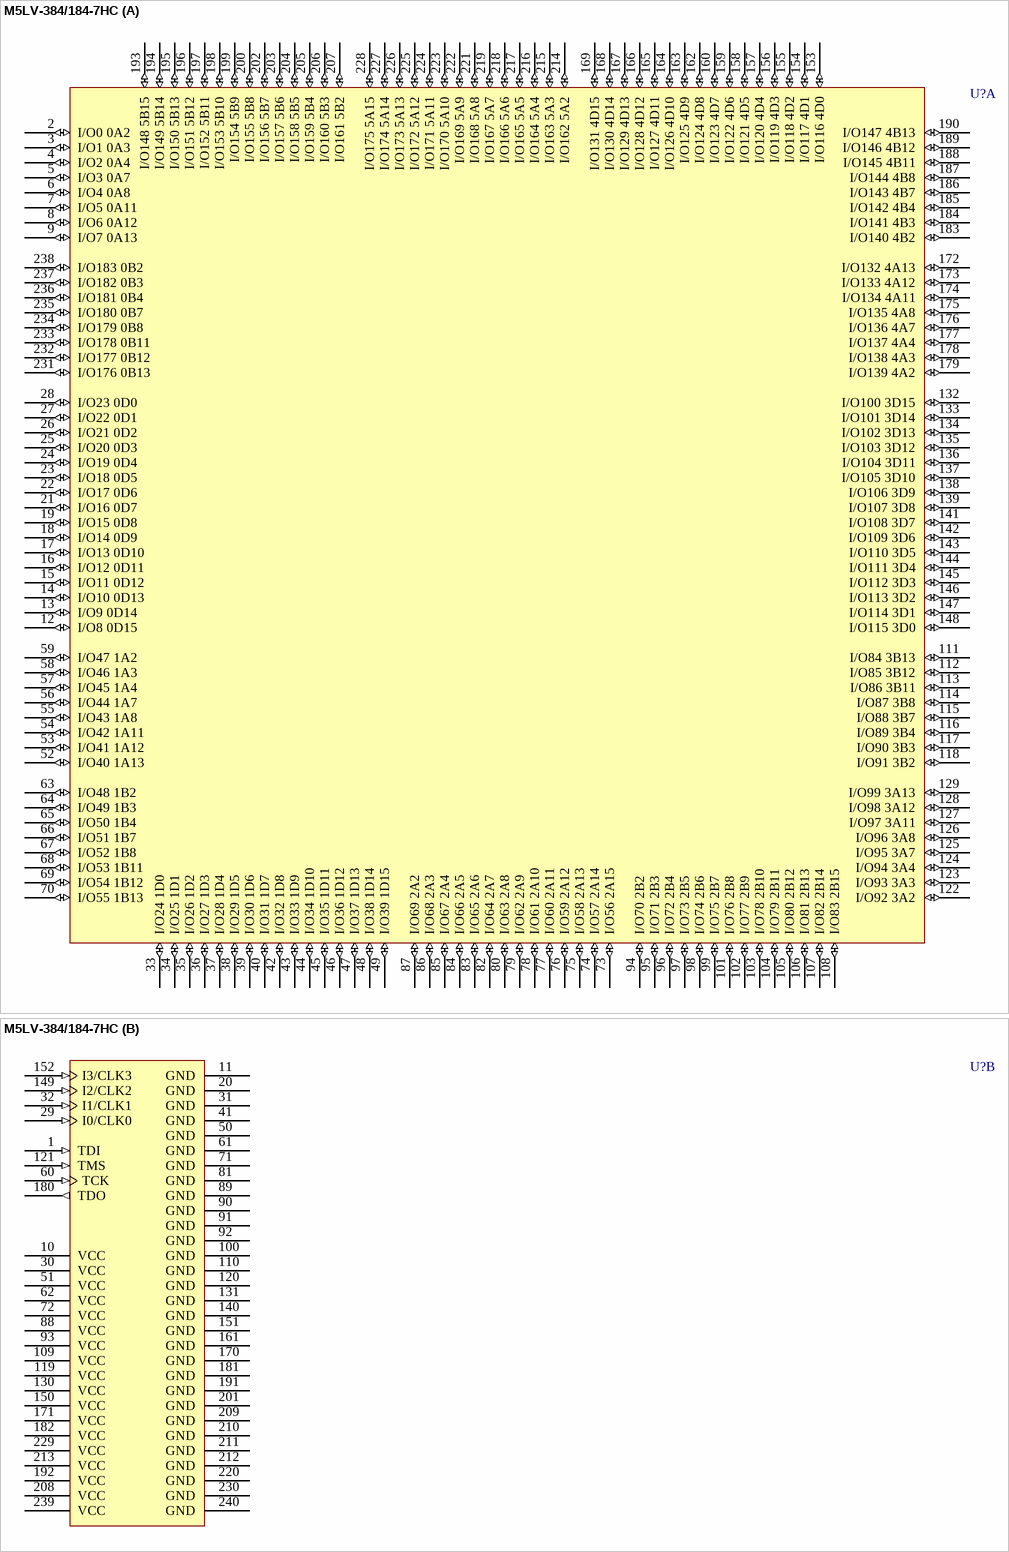
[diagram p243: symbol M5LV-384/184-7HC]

## M5LV-384/184-7HC
designator U?
High-Density and High-I/O Complex PLD
footprint PQFP240_N (Shrink QFP, 240-Leads, Body 32x32mm, Pitch 0.5mm, IPC Medium Density)
footprint PQFP240_L (Shrink QFP, 240-Leads, Body 32x32mm, Pitch 0.5mm, IPC High Density)
footprint PQFP240_M (Shrink QFP, 240-Leads, Body 32x32mm, Pitch 0.5mm, IPC Low Density)
3D model M5LV-PQFP240 (240-Pin Shrink Quad Flat Pack 0.5 mm Pitch)
part A pins: 2 I/O0 0A2 (io), 3 I/O1 0A3 (io), 4 I/O2 0A4 (io), 5 I/O3 0A7 (io), 6 I/O4 0A8 (io), 7 I/O5 0A11 (io), 8 I/O6 0A12 (io), 9 I/O7 0A13 (io), 12 I/O8 0D15 (io), 13 I/O9 0D14 (io), 14 I/O10 0D13 (io), 15 I/O11 0D12 (io), 16 I/O12 0D11 (io), 17 I/O13 0D10 (io), 18 I/O14 0D9 (io), 19 I/O15 0D8 (io), 21 I/O16 0D7 (io), 22 I/O17 0D6 (io), 23 I/O18 0D5 (io), 24 I/O19 0D4 (io), 25 I/O20 0D3 (io), 26 I/O21 0D2 (io), 27 I/O22 0D1 (io), 28 I/O23 0D0 (io), 33 I/O24 1D0 (io), 34 I/O25 1D1 (io), 35 I/O26 1D2 (io), 36 I/O27 1D3 (io), 37 I/O28 1D4 (io), 38 I/O29 1D5 (io), 39 I/O30 1D6 (io), 40 I/O31 1D7 (io), 42 I/O32 1D8 (io), 43 I/O33 1D9 (io), 44 I/O34 1D10 (io), 45 I/O35 1D11 (io), 46 I/O36 1D12 (io), 47 I/O37 1D13 (io), 48 I/O38 1D14 (io), 49 I/O39 1D15 (io), 52 I/O40 1A13 (io), 53 I/O41 1A12 (io), 54 I/O42 1A11 (io), 55 I/O43 1A8 (io), 56 I/O44 1A7 (io), 57 I/O45 1A4 (io), 58 I/O46 1A3 (io), 59 I/O47 1A2 (io), 63 I/O48 1B2 (io), 64 I/O49 1B3 (io), 65 I/O50 1B4 (io), 66 I/O51 1B7 (io), 67 I/O52 1B8 (io), 68 I/O53 1B11 (io), 69 I/O54 1B12 (io), 70 I/O55 1B13 (io), 73 I/O56 2A15 (io), 74 I/O57 2A14 (io), 75 I/O58 2A13 (io), 76 I/O59 2A12 (io), 77 I/O60 2A11 (io), 78 I/O61 2A10 (io), 79 I/O62 2A9 (io), 80 I/O63 2A8 (io), 82 I/O64 2A7 (io), 83 I/O65 2A6 (io), 84 I/O66 2A5 (io), 85 I/O67 2A4 (io), 86 I/O68 2A3 (io), 87 I/O69 2A2 (io), 94 I/O70 2B2 (io), 95 I/O71 2B3 (io), 96 I/O72 2B4 (io), 97 I/O73 2B5 (io), 98 I/O74 2B6 (io), 99 I/O75 2B7 (io), 101 I/O76 2B8 (io), 102 I/O77 2B9 (io), 103 I/O78 2B10 (io), 104 I/O79 2B11 (io), 105 I/O80 2B12 (io), 106 I/O81 2B13 (io), 107 I/O82 2B14 (io), 108 I/O83 2B15 (io), 111 I/O84 3B13 (io), 112 I/O85 3B12 (io), 113 I/O86 3B11 (io), 114 I/O87 3B8 (io), 115 I/O88 3B7 (io), 116 I/O89 3B4 (io), 117 I/O90 3B3 (io), 118 I/O91 3B2 (io), 122 I/O92 3A2 (io), 123 I/O93 3A3 (io), 124 I/O94 3A4 (io), 125 I/O95 3A7 (io), 126 I/O96 3A8 (io), 127 I/O97 3A11 (io), 128 I/O98 3A12 (io), 129 I/O99 3A13 (io), 132 I/O100 3D15 (io), 133 I/O101 3D14 (io), 134 I/O102 3D13 (io), 135 I/O103 3D12 (io), 136 I/O104 3D11 (io), 137 I/O105 3D10 (io), 138 I/O106 3D9 (io), 139 I/O107 3D8 (io), 141 I/O108 3D7 (io), 142 I/O109 3D6 (io), 143 I/O110 3D5 (io), 144 I/O111 3D4 (io), 145 I/O112 3D3 (io), 146 I/O113 3D2 (io), 147 I/O114 3D1 (io), 148 I/O115 3D0 (io), 153 I/O116 4D0 (io), 154 I/O117 4D1 (io), 155 I/O118 4D2 (io), 156 I/O119 4D3 (io), 157 I/O120 4D4 (io), 158 I/O121 4D5 (io), 159 I/O122 4D6 (io), 160 I/O123 4D7 (io), 162 I/O124 4D8 (io), 163 I/O125 4D9 (io), 164 I/O126 4D10 (io), 165 I/O127 4D11 (io), 166 I/O128 4D12 (io), 167 I/O129 4D13 (io), 168 I/O130 4D14 (io), 169 I/O131 4D15 (io), 172 I/O132 4A13 (io), 173 I/O133 4A12 (io), 174 I/O134 4A11 (io), 175 I/O135 4A8 (io), 176 I/O136 4A7 (io), 177 I/O137 4A4 (io), 178 I/O138 4A3 (io), 179 I/O139 4A2 (io), 183 I/O140 4B2 (io), 184 I/O141 4B3 (io), 185 I/O142 4B4 (io), 186 I/O143 4B7 (io), 187 I/O144 4B8 (io), 188 I/O145 4B11 (io), 189 I/O146 4B12 (io), 190 I/O147 4B13 (io), 193 I/O148 5B15 (io), 194 I/O149 5B14 (io), 195 I/O150 5B13 (io), 196 I/O151 5B12 (io), 197 I/O152 5B11 (io), 198 I/O153 5B10 (io), 199 I/O154 5B9 (io), 200 I/O155 5B8 (io), 202 I/O156 5B7 (io), 203 I/O157 5B6 (io), 204 I/O158 5B5 (io), 205 I/O159 5B4 (io), 206 I/O160 5B3 (io), 207 I/O161 5B2 (io), 214 I/O162 5A2 (io), 215 I/O163 5A3 (io), 216 I/O164 5A4 (io), 217 I/O165 5A5 (io), 218 I/O166 5A6 (io), 219 I/O167 5A7 (io), 221 I/O168 5A8 (io), 222 I/O169 5A9 (io), 223 I/O170 5A10 (io), 224 I/O171 5A11 (io), 225 I/O172 5A12 (io), 226 I/O173 5A13 (io), 227 I/O174 5A14 (io), 228 I/O175 5A15 (io), 231 I/O176 0B13 (io), 232 I/O177 0B12 (io), 233 I/O178 0B11 (io), 234 I/O179 0B8 (io), 235 I/O180 0B7 (io), 236 I/O181 0B4 (io), 237 I/O182 0B3 (io), 238 I/O183 0B2 (io)
part B pins: 1 TDI (in), 10 VCC (power), 11 GND (power), 20 GND (power), 29 I0/CLK0 (in), 30 VCC (power), 31 GND (power), 32 I1/CLK1 (in), 41 GND (power), 50 GND (power), 51 VCC (power), 60 TCK (in), 61 GND (power), 62 VCC (power), 71 GND (power), 72 VCC (power), 81 GND (power), 88 VCC (power), 89 GND (power), 90 GND (power), 91 GND (power), 92 GND (power), 93 VCC (power), 100 GND (power), 109 VCC (power), 110 GND (power), 119 VCC (power), 120 GND (power), 121 TMS (in), 130 VCC (power), 131 GND (power), 140 GND (power), 149 I2/CLK2 (in), 150 VCC (power), 151 GND (power), 152 I3/CLK3 (in), 161 GND (power), 170 GND (power), 171 VCC (power), 180 TDO (out), 181 GND (power), 182 VCC (power), 191 GND (power), 192 VCC (power), 201 GND (power), 208 VCC (power), 209 GND (power), 210 GND (power), 211 GND (power), 212 GND (power), 213 VCC (power), 220 GND (power), 229 VCC (power), 230 GND (power), 239 VCC (power), 240 GND (power)

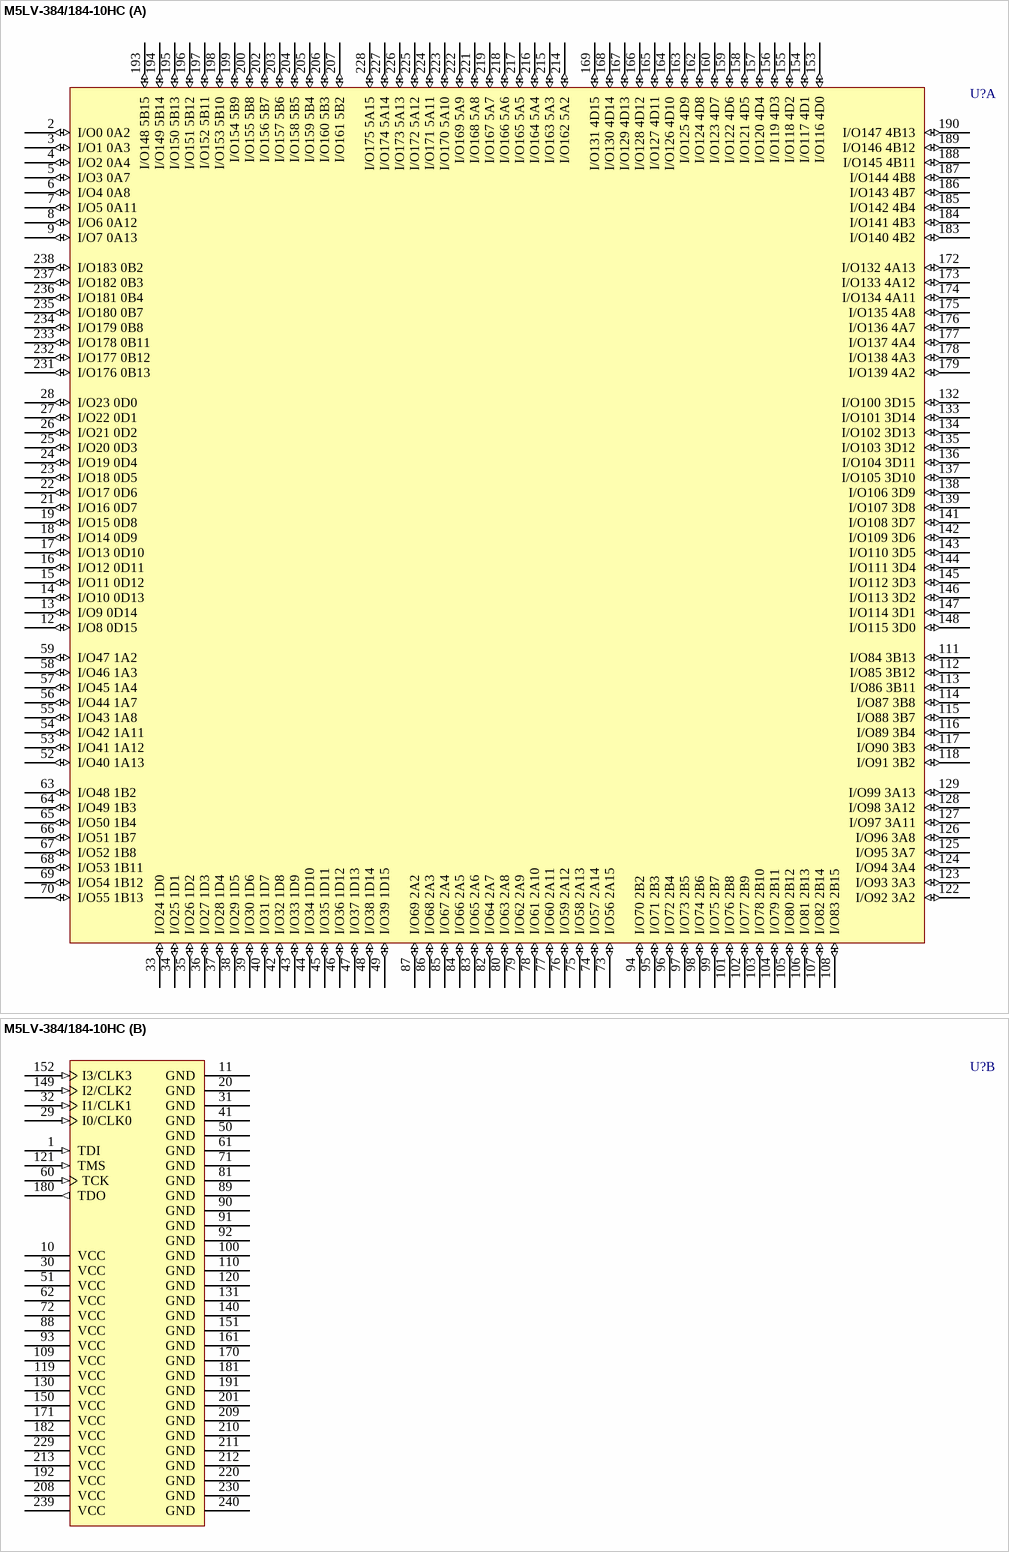
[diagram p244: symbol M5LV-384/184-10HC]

## M5LV-384/184-10HC
designator U?
High-Density and High-I/O Complex PLD
footprint PQFP240_N (Shrink QFP, 240-Leads, Body 32x32mm, Pitch 0.5mm, IPC Medium Density)
footprint PQFP240_L (Shrink QFP, 240-Leads, Body 32x32mm, Pitch 0.5mm, IPC High Density)
footprint PQFP240_M (Shrink QFP, 240-Leads, Body 32x32mm, Pitch 0.5mm, IPC Low Density)
3D model M5LV-PQFP240 (240-Pin Shrink Quad Flat Pack 0.5 mm Pitch)
part A pins: 2 I/O0 0A2 (io), 3 I/O1 0A3 (io), 4 I/O2 0A4 (io), 5 I/O3 0A7 (io), 6 I/O4 0A8 (io), 7 I/O5 0A11 (io), 8 I/O6 0A12 (io), 9 I/O7 0A13 (io), 12 I/O8 0D15 (io), 13 I/O9 0D14 (io), 14 I/O10 0D13 (io), 15 I/O11 0D12 (io), 16 I/O12 0D11 (io), 17 I/O13 0D10 (io), 18 I/O14 0D9 (io), 19 I/O15 0D8 (io), 21 I/O16 0D7 (io), 22 I/O17 0D6 (io), 23 I/O18 0D5 (io), 24 I/O19 0D4 (io), 25 I/O20 0D3 (io), 26 I/O21 0D2 (io), 27 I/O22 0D1 (io), 28 I/O23 0D0 (io), 33 I/O24 1D0 (io), 34 I/O25 1D1 (io), 35 I/O26 1D2 (io), 36 I/O27 1D3 (io), 37 I/O28 1D4 (io), 38 I/O29 1D5 (io), 39 I/O30 1D6 (io), 40 I/O31 1D7 (io), 42 I/O32 1D8 (io), 43 I/O33 1D9 (io), 44 I/O34 1D10 (io), 45 I/O35 1D11 (io), 46 I/O36 1D12 (io), 47 I/O37 1D13 (io), 48 I/O38 1D14 (io), 49 I/O39 1D15 (io), 52 I/O40 1A13 (io), 53 I/O41 1A12 (io), 54 I/O42 1A11 (io), 55 I/O43 1A8 (io), 56 I/O44 1A7 (io), 57 I/O45 1A4 (io), 58 I/O46 1A3 (io), 59 I/O47 1A2 (io), 63 I/O48 1B2 (io), 64 I/O49 1B3 (io), 65 I/O50 1B4 (io), 66 I/O51 1B7 (io), 67 I/O52 1B8 (io), 68 I/O53 1B11 (io), 69 I/O54 1B12 (io), 70 I/O55 1B13 (io), 73 I/O56 2A15 (io), 74 I/O57 2A14 (io), 75 I/O58 2A13 (io), 76 I/O59 2A12 (io), 77 I/O60 2A11 (io), 78 I/O61 2A10 (io), 79 I/O62 2A9 (io), 80 I/O63 2A8 (io), 82 I/O64 2A7 (io), 83 I/O65 2A6 (io), 84 I/O66 2A5 (io), 85 I/O67 2A4 (io), 86 I/O68 2A3 (io), 87 I/O69 2A2 (io), 94 I/O70 2B2 (io), 95 I/O71 2B3 (io), 96 I/O72 2B4 (io), 97 I/O73 2B5 (io), 98 I/O74 2B6 (io), 99 I/O75 2B7 (io), 101 I/O76 2B8 (io), 102 I/O77 2B9 (io), 103 I/O78 2B10 (io), 104 I/O79 2B11 (io), 105 I/O80 2B12 (io), 106 I/O81 2B13 (io), 107 I/O82 2B14 (io), 108 I/O83 2B15 (io), 111 I/O84 3B13 (io), 112 I/O85 3B12 (io), 113 I/O86 3B11 (io), 114 I/O87 3B8 (io), 115 I/O88 3B7 (io), 116 I/O89 3B4 (io), 117 I/O90 3B3 (io), 118 I/O91 3B2 (io), 122 I/O92 3A2 (io), 123 I/O93 3A3 (io), 124 I/O94 3A4 (io), 125 I/O95 3A7 (io), 126 I/O96 3A8 (io), 127 I/O97 3A11 (io), 128 I/O98 3A12 (io), 129 I/O99 3A13 (io), 132 I/O100 3D15 (io), 133 I/O101 3D14 (io), 134 I/O102 3D13 (io), 135 I/O103 3D12 (io), 136 I/O104 3D11 (io), 137 I/O105 3D10 (io), 138 I/O106 3D9 (io), 139 I/O107 3D8 (io), 141 I/O108 3D7 (io), 142 I/O109 3D6 (io), 143 I/O110 3D5 (io), 144 I/O111 3D4 (io), 145 I/O112 3D3 (io), 146 I/O113 3D2 (io), 147 I/O114 3D1 (io), 148 I/O115 3D0 (io), 153 I/O116 4D0 (io), 154 I/O117 4D1 (io), 155 I/O118 4D2 (io), 156 I/O119 4D3 (io), 157 I/O120 4D4 (io), 158 I/O121 4D5 (io), 159 I/O122 4D6 (io), 160 I/O123 4D7 (io), 162 I/O124 4D8 (io), 163 I/O125 4D9 (io), 164 I/O126 4D10 (io), 165 I/O127 4D11 (io), 166 I/O128 4D12 (io), 167 I/O129 4D13 (io), 168 I/O130 4D14 (io), 169 I/O131 4D15 (io), 172 I/O132 4A13 (io), 173 I/O133 4A12 (io), 174 I/O134 4A11 (io), 175 I/O135 4A8 (io), 176 I/O136 4A7 (io), 177 I/O137 4A4 (io), 178 I/O138 4A3 (io), 179 I/O139 4A2 (io), 183 I/O140 4B2 (io), 184 I/O141 4B3 (io), 185 I/O142 4B4 (io), 186 I/O143 4B7 (io), 187 I/O144 4B8 (io), 188 I/O145 4B11 (io), 189 I/O146 4B12 (io), 190 I/O147 4B13 (io), 193 I/O148 5B15 (io), 194 I/O149 5B14 (io), 195 I/O150 5B13 (io), 196 I/O151 5B12 (io), 197 I/O152 5B11 (io), 198 I/O153 5B10 (io), 199 I/O154 5B9 (io), 200 I/O155 5B8 (io), 202 I/O156 5B7 (io), 203 I/O157 5B6 (io), 204 I/O158 5B5 (io), 205 I/O159 5B4 (io), 206 I/O160 5B3 (io), 207 I/O161 5B2 (io), 214 I/O162 5A2 (io), 215 I/O163 5A3 (io), 216 I/O164 5A4 (io), 217 I/O165 5A5 (io), 218 I/O166 5A6 (io), 219 I/O167 5A7 (io), 221 I/O168 5A8 (io), 222 I/O169 5A9 (io), 223 I/O170 5A10 (io), 224 I/O171 5A11 (io), 225 I/O172 5A12 (io), 226 I/O173 5A13 (io), 227 I/O174 5A14 (io), 228 I/O175 5A15 (io), 231 I/O176 0B13 (io), 232 I/O177 0B12 (io), 233 I/O178 0B11 (io), 234 I/O179 0B8 (io), 235 I/O180 0B7 (io), 236 I/O181 0B4 (io), 237 I/O182 0B3 (io), 238 I/O183 0B2 (io)
part B pins: 1 TDI (in), 10 VCC (power), 11 GND (power), 20 GND (power), 29 I0/CLK0 (in), 30 VCC (power), 31 GND (power), 32 I1/CLK1 (in), 41 GND (power), 50 GND (power), 51 VCC (power), 60 TCK (in), 61 GND (power), 62 VCC (power), 71 GND (power), 72 VCC (power), 81 GND (power), 88 VCC (power), 89 GND (power), 90 GND (power), 91 GND (power), 92 GND (power), 93 VCC (power), 100 GND (power), 109 VCC (power), 110 GND (power), 119 VCC (power), 120 GND (power), 121 TMS (in), 130 VCC (power), 131 GND (power), 140 GND (power), 149 I2/CLK2 (in), 150 VCC (power), 151 GND (power), 152 I3/CLK3 (in), 161 GND (power), 170 GND (power), 171 VCC (power), 180 TDO (out), 181 GND (power), 182 VCC (power), 191 GND (power), 192 VCC (power), 201 GND (power), 208 VCC (power), 209 GND (power), 210 GND (power), 211 GND (power), 212 GND (power), 213 VCC (power), 220 GND (power), 229 VCC (power), 230 GND (power), 239 VCC (power), 240 GND (power)

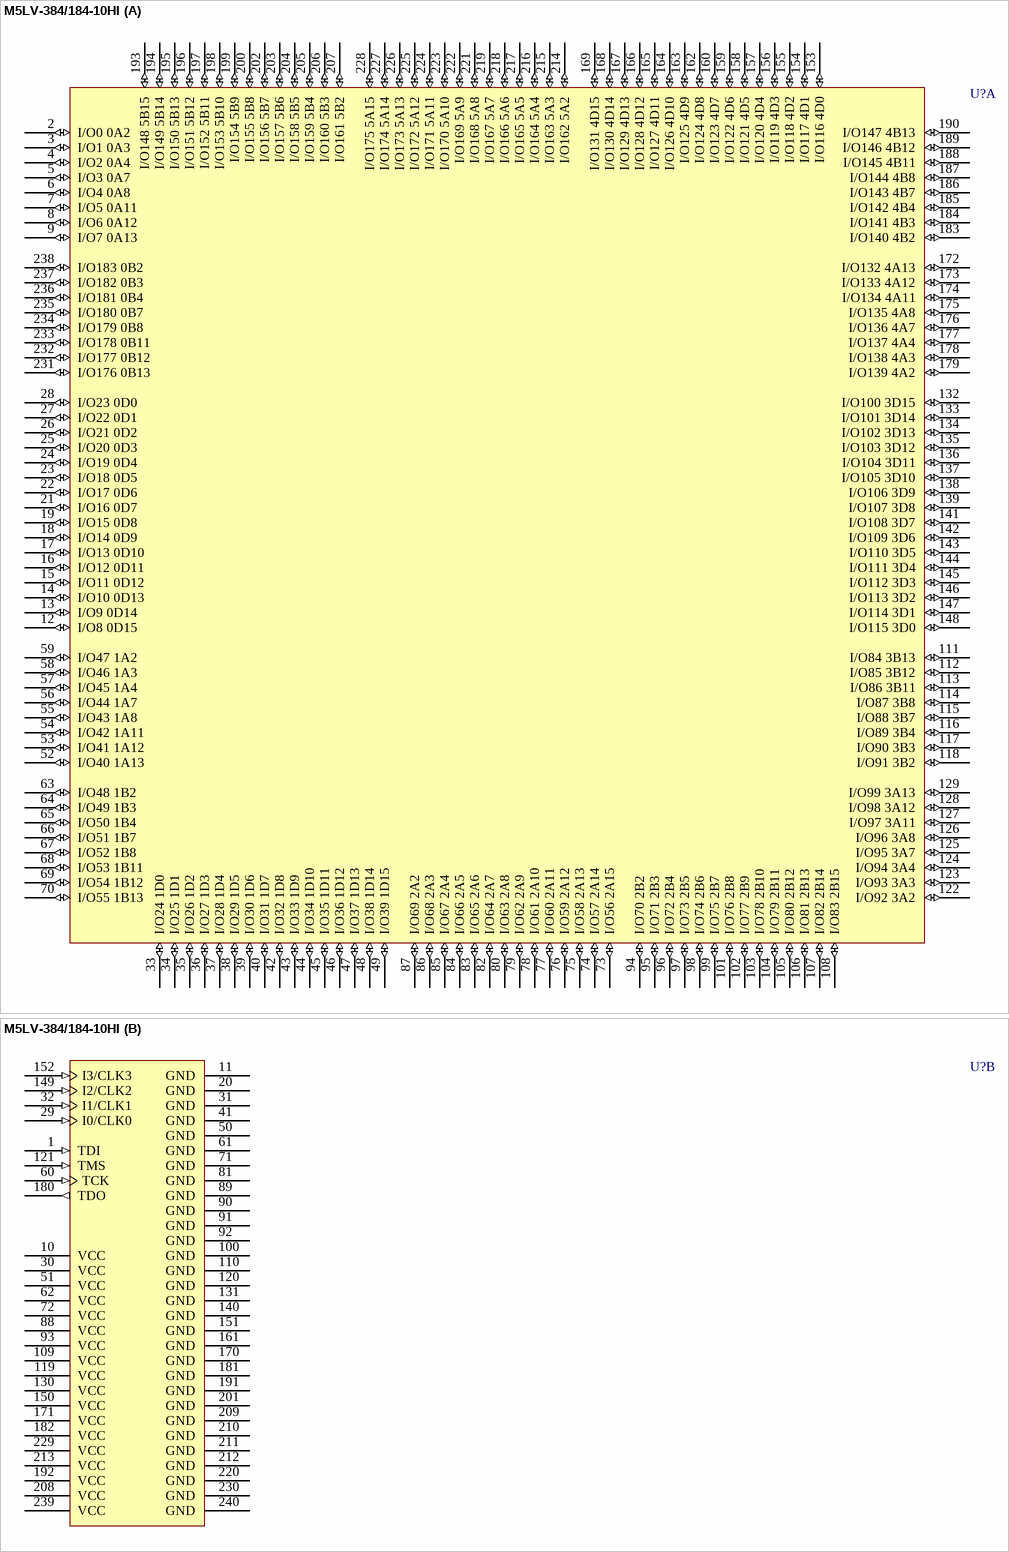
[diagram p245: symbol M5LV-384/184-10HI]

## M5LV-384/184-10HI
designator U?
High-Density and High-I/O Complex PLD
footprint PQFP240_N (Shrink QFP, 240-Leads, Body 32x32mm, Pitch 0.5mm, IPC Medium Density)
footprint PQFP240_L (Shrink QFP, 240-Leads, Body 32x32mm, Pitch 0.5mm, IPC High Density)
footprint PQFP240_M (Shrink QFP, 240-Leads, Body 32x32mm, Pitch 0.5mm, IPC Low Density)
3D model M5LV-PQFP240 (240-Pin Shrink Quad Flat Pack 0.5 mm Pitch)
part A pins: 2 I/O0 0A2 (io), 3 I/O1 0A3 (io), 4 I/O2 0A4 (io), 5 I/O3 0A7 (io), 6 I/O4 0A8 (io), 7 I/O5 0A11 (io), 8 I/O6 0A12 (io), 9 I/O7 0A13 (io), 12 I/O8 0D15 (io), 13 I/O9 0D14 (io), 14 I/O10 0D13 (io), 15 I/O11 0D12 (io), 16 I/O12 0D11 (io), 17 I/O13 0D10 (io), 18 I/O14 0D9 (io), 19 I/O15 0D8 (io), 21 I/O16 0D7 (io), 22 I/O17 0D6 (io), 23 I/O18 0D5 (io), 24 I/O19 0D4 (io), 25 I/O20 0D3 (io), 26 I/O21 0D2 (io), 27 I/O22 0D1 (io), 28 I/O23 0D0 (io), 33 I/O24 1D0 (io), 34 I/O25 1D1 (io), 35 I/O26 1D2 (io), 36 I/O27 1D3 (io), 37 I/O28 1D4 (io), 38 I/O29 1D5 (io), 39 I/O30 1D6 (io), 40 I/O31 1D7 (io), 42 I/O32 1D8 (io), 43 I/O33 1D9 (io), 44 I/O34 1D10 (io), 45 I/O35 1D11 (io), 46 I/O36 1D12 (io), 47 I/O37 1D13 (io), 48 I/O38 1D14 (io), 49 I/O39 1D15 (io), 52 I/O40 1A13 (io), 53 I/O41 1A12 (io), 54 I/O42 1A11 (io), 55 I/O43 1A8 (io), 56 I/O44 1A7 (io), 57 I/O45 1A4 (io), 58 I/O46 1A3 (io), 59 I/O47 1A2 (io), 63 I/O48 1B2 (io), 64 I/O49 1B3 (io), 65 I/O50 1B4 (io), 66 I/O51 1B7 (io), 67 I/O52 1B8 (io), 68 I/O53 1B11 (io), 69 I/O54 1B12 (io), 70 I/O55 1B13 (io), 73 I/O56 2A15 (io), 74 I/O57 2A14 (io), 75 I/O58 2A13 (io), 76 I/O59 2A12 (io), 77 I/O60 2A11 (io), 78 I/O61 2A10 (io), 79 I/O62 2A9 (io), 80 I/O63 2A8 (io), 82 I/O64 2A7 (io), 83 I/O65 2A6 (io), 84 I/O66 2A5 (io), 85 I/O67 2A4 (io), 86 I/O68 2A3 (io), 87 I/O69 2A2 (io), 94 I/O70 2B2 (io), 95 I/O71 2B3 (io), 96 I/O72 2B4 (io), 97 I/O73 2B5 (io), 98 I/O74 2B6 (io), 99 I/O75 2B7 (io), 101 I/O76 2B8 (io), 102 I/O77 2B9 (io), 103 I/O78 2B10 (io), 104 I/O79 2B11 (io), 105 I/O80 2B12 (io), 106 I/O81 2B13 (io), 107 I/O82 2B14 (io), 108 I/O83 2B15 (io), 111 I/O84 3B13 (io), 112 I/O85 3B12 (io), 113 I/O86 3B11 (io), 114 I/O87 3B8 (io), 115 I/O88 3B7 (io), 116 I/O89 3B4 (io), 117 I/O90 3B3 (io), 118 I/O91 3B2 (io), 122 I/O92 3A2 (io), 123 I/O93 3A3 (io), 124 I/O94 3A4 (io), 125 I/O95 3A7 (io), 126 I/O96 3A8 (io), 127 I/O97 3A11 (io), 128 I/O98 3A12 (io), 129 I/O99 3A13 (io), 132 I/O100 3D15 (io), 133 I/O101 3D14 (io), 134 I/O102 3D13 (io), 135 I/O103 3D12 (io), 136 I/O104 3D11 (io), 137 I/O105 3D10 (io), 138 I/O106 3D9 (io), 139 I/O107 3D8 (io), 141 I/O108 3D7 (io), 142 I/O109 3D6 (io), 143 I/O110 3D5 (io), 144 I/O111 3D4 (io), 145 I/O112 3D3 (io), 146 I/O113 3D2 (io), 147 I/O114 3D1 (io), 148 I/O115 3D0 (io), 153 I/O116 4D0 (io), 154 I/O117 4D1 (io), 155 I/O118 4D2 (io), 156 I/O119 4D3 (io), 157 I/O120 4D4 (io), 158 I/O121 4D5 (io), 159 I/O122 4D6 (io), 160 I/O123 4D7 (io), 162 I/O124 4D8 (io), 163 I/O125 4D9 (io), 164 I/O126 4D10 (io), 165 I/O127 4D11 (io), 166 I/O128 4D12 (io), 167 I/O129 4D13 (io), 168 I/O130 4D14 (io), 169 I/O131 4D15 (io), 172 I/O132 4A13 (io), 173 I/O133 4A12 (io), 174 I/O134 4A11 (io), 175 I/O135 4A8 (io), 176 I/O136 4A7 (io), 177 I/O137 4A4 (io), 178 I/O138 4A3 (io), 179 I/O139 4A2 (io), 183 I/O140 4B2 (io), 184 I/O141 4B3 (io), 185 I/O142 4B4 (io), 186 I/O143 4B7 (io), 187 I/O144 4B8 (io), 188 I/O145 4B11 (io), 189 I/O146 4B12 (io), 190 I/O147 4B13 (io), 193 I/O148 5B15 (io), 194 I/O149 5B14 (io), 195 I/O150 5B13 (io), 196 I/O151 5B12 (io), 197 I/O152 5B11 (io), 198 I/O153 5B10 (io), 199 I/O154 5B9 (io), 200 I/O155 5B8 (io), 202 I/O156 5B7 (io), 203 I/O157 5B6 (io), 204 I/O158 5B5 (io), 205 I/O159 5B4 (io), 206 I/O160 5B3 (io), 207 I/O161 5B2 (io), 214 I/O162 5A2 (io), 215 I/O163 5A3 (io), 216 I/O164 5A4 (io), 217 I/O165 5A5 (io), 218 I/O166 5A6 (io), 219 I/O167 5A7 (io), 221 I/O168 5A8 (io), 222 I/O169 5A9 (io), 223 I/O170 5A10 (io), 224 I/O171 5A11 (io), 225 I/O172 5A12 (io), 226 I/O173 5A13 (io), 227 I/O174 5A14 (io), 228 I/O175 5A15 (io), 231 I/O176 0B13 (io), 232 I/O177 0B12 (io), 233 I/O178 0B11 (io), 234 I/O179 0B8 (io), 235 I/O180 0B7 (io), 236 I/O181 0B4 (io), 237 I/O182 0B3 (io), 238 I/O183 0B2 (io)
part B pins: 1 TDI (in), 10 VCC (power), 11 GND (power), 20 GND (power), 29 I0/CLK0 (in), 30 VCC (power), 31 GND (power), 32 I1/CLK1 (in), 41 GND (power), 50 GND (power), 51 VCC (power), 60 TCK (in), 61 GND (power), 62 VCC (power), 71 GND (power), 72 VCC (power), 81 GND (power), 88 VCC (power), 89 GND (power), 90 GND (power), 91 GND (power), 92 GND (power), 93 VCC (power), 100 GND (power), 109 VCC (power), 110 GND (power), 119 VCC (power), 120 GND (power), 121 TMS (in), 130 VCC (power), 131 GND (power), 140 GND (power), 149 I2/CLK2 (in), 150 VCC (power), 151 GND (power), 152 I3/CLK3 (in), 161 GND (power), 170 GND (power), 171 VCC (power), 180 TDO (out), 181 GND (power), 182 VCC (power), 191 GND (power), 192 VCC (power), 201 GND (power), 208 VCC (power), 209 GND (power), 210 GND (power), 211 GND (power), 212 GND (power), 213 VCC (power), 220 GND (power), 229 VCC (power), 230 GND (power), 239 VCC (power), 240 GND (power)

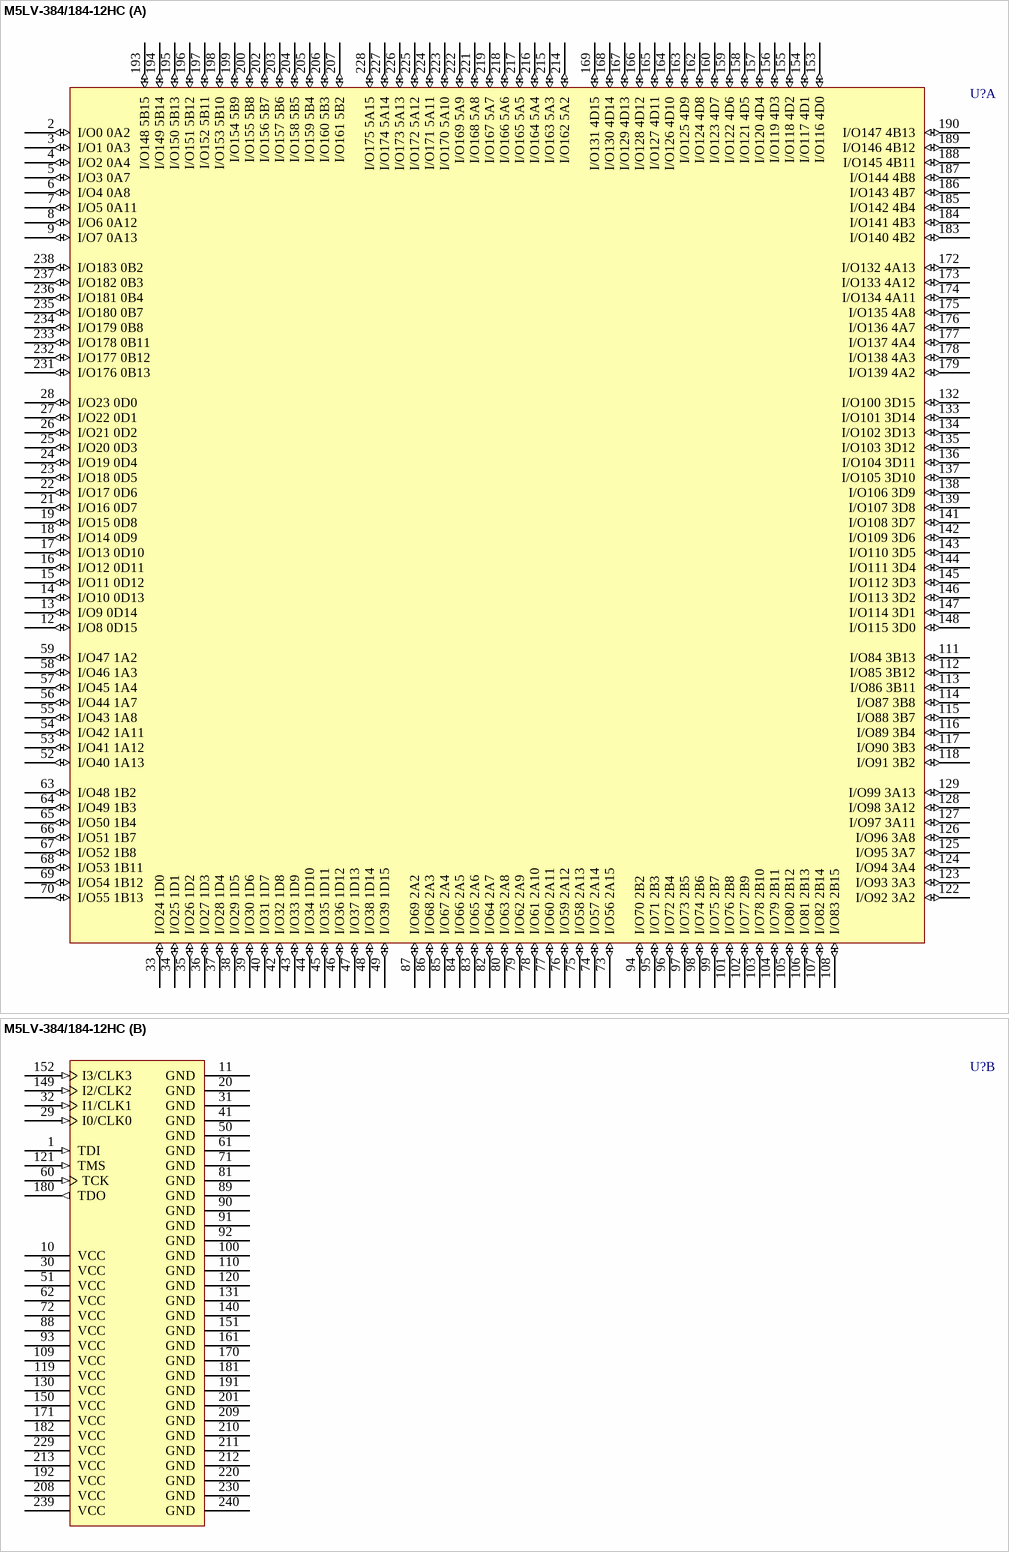
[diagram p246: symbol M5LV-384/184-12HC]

## M5LV-384/184-12HC
designator U?
High-Density and High-I/O Complex PLD
footprint PQFP240_N (Shrink QFP, 240-Leads, Body 32x32mm, Pitch 0.5mm, IPC Medium Density)
footprint PQFP240_L (Shrink QFP, 240-Leads, Body 32x32mm, Pitch 0.5mm, IPC High Density)
footprint PQFP240_M (Shrink QFP, 240-Leads, Body 32x32mm, Pitch 0.5mm, IPC Low Density)
3D model M5LV-PQFP240 (240-Pin Shrink Quad Flat Pack 0.5 mm Pitch)
part A pins: 2 I/O0 0A2 (io), 3 I/O1 0A3 (io), 4 I/O2 0A4 (io), 5 I/O3 0A7 (io), 6 I/O4 0A8 (io), 7 I/O5 0A11 (io), 8 I/O6 0A12 (io), 9 I/O7 0A13 (io), 12 I/O8 0D15 (io), 13 I/O9 0D14 (io), 14 I/O10 0D13 (io), 15 I/O11 0D12 (io), 16 I/O12 0D11 (io), 17 I/O13 0D10 (io), 18 I/O14 0D9 (io), 19 I/O15 0D8 (io), 21 I/O16 0D7 (io), 22 I/O17 0D6 (io), 23 I/O18 0D5 (io), 24 I/O19 0D4 (io), 25 I/O20 0D3 (io), 26 I/O21 0D2 (io), 27 I/O22 0D1 (io), 28 I/O23 0D0 (io), 33 I/O24 1D0 (io), 34 I/O25 1D1 (io), 35 I/O26 1D2 (io), 36 I/O27 1D3 (io), 37 I/O28 1D4 (io), 38 I/O29 1D5 (io), 39 I/O30 1D6 (io), 40 I/O31 1D7 (io), 42 I/O32 1D8 (io), 43 I/O33 1D9 (io), 44 I/O34 1D10 (io), 45 I/O35 1D11 (io), 46 I/O36 1D12 (io), 47 I/O37 1D13 (io), 48 I/O38 1D14 (io), 49 I/O39 1D15 (io), 52 I/O40 1A13 (io), 53 I/O41 1A12 (io), 54 I/O42 1A11 (io), 55 I/O43 1A8 (io), 56 I/O44 1A7 (io), 57 I/O45 1A4 (io), 58 I/O46 1A3 (io), 59 I/O47 1A2 (io), 63 I/O48 1B2 (io), 64 I/O49 1B3 (io), 65 I/O50 1B4 (io), 66 I/O51 1B7 (io), 67 I/O52 1B8 (io), 68 I/O53 1B11 (io), 69 I/O54 1B12 (io), 70 I/O55 1B13 (io), 73 I/O56 2A15 (io), 74 I/O57 2A14 (io), 75 I/O58 2A13 (io), 76 I/O59 2A12 (io), 77 I/O60 2A11 (io), 78 I/O61 2A10 (io), 79 I/O62 2A9 (io), 80 I/O63 2A8 (io), 82 I/O64 2A7 (io), 83 I/O65 2A6 (io), 84 I/O66 2A5 (io), 85 I/O67 2A4 (io), 86 I/O68 2A3 (io), 87 I/O69 2A2 (io), 94 I/O70 2B2 (io), 95 I/O71 2B3 (io), 96 I/O72 2B4 (io), 97 I/O73 2B5 (io), 98 I/O74 2B6 (io), 99 I/O75 2B7 (io), 101 I/O76 2B8 (io), 102 I/O77 2B9 (io), 103 I/O78 2B10 (io), 104 I/O79 2B11 (io), 105 I/O80 2B12 (io), 106 I/O81 2B13 (io), 107 I/O82 2B14 (io), 108 I/O83 2B15 (io), 111 I/O84 3B13 (io), 112 I/O85 3B12 (io), 113 I/O86 3B11 (io), 114 I/O87 3B8 (io), 115 I/O88 3B7 (io), 116 I/O89 3B4 (io), 117 I/O90 3B3 (io), 118 I/O91 3B2 (io), 122 I/O92 3A2 (io), 123 I/O93 3A3 (io), 124 I/O94 3A4 (io), 125 I/O95 3A7 (io), 126 I/O96 3A8 (io), 127 I/O97 3A11 (io), 128 I/O98 3A12 (io), 129 I/O99 3A13 (io), 132 I/O100 3D15 (io), 133 I/O101 3D14 (io), 134 I/O102 3D13 (io), 135 I/O103 3D12 (io), 136 I/O104 3D11 (io), 137 I/O105 3D10 (io), 138 I/O106 3D9 (io), 139 I/O107 3D8 (io), 141 I/O108 3D7 (io), 142 I/O109 3D6 (io), 143 I/O110 3D5 (io), 144 I/O111 3D4 (io), 145 I/O112 3D3 (io), 146 I/O113 3D2 (io), 147 I/O114 3D1 (io), 148 I/O115 3D0 (io), 153 I/O116 4D0 (io), 154 I/O117 4D1 (io), 155 I/O118 4D2 (io), 156 I/O119 4D3 (io), 157 I/O120 4D4 (io), 158 I/O121 4D5 (io), 159 I/O122 4D6 (io), 160 I/O123 4D7 (io), 162 I/O124 4D8 (io), 163 I/O125 4D9 (io), 164 I/O126 4D10 (io), 165 I/O127 4D11 (io), 166 I/O128 4D12 (io), 167 I/O129 4D13 (io), 168 I/O130 4D14 (io), 169 I/O131 4D15 (io), 172 I/O132 4A13 (io), 173 I/O133 4A12 (io), 174 I/O134 4A11 (io), 175 I/O135 4A8 (io), 176 I/O136 4A7 (io), 177 I/O137 4A4 (io), 178 I/O138 4A3 (io), 179 I/O139 4A2 (io), 183 I/O140 4B2 (io), 184 I/O141 4B3 (io), 185 I/O142 4B4 (io), 186 I/O143 4B7 (io), 187 I/O144 4B8 (io), 188 I/O145 4B11 (io), 189 I/O146 4B12 (io), 190 I/O147 4B13 (io), 193 I/O148 5B15 (io), 194 I/O149 5B14 (io), 195 I/O150 5B13 (io), 196 I/O151 5B12 (io), 197 I/O152 5B11 (io), 198 I/O153 5B10 (io), 199 I/O154 5B9 (io), 200 I/O155 5B8 (io), 202 I/O156 5B7 (io), 203 I/O157 5B6 (io), 204 I/O158 5B5 (io), 205 I/O159 5B4 (io), 206 I/O160 5B3 (io), 207 I/O161 5B2 (io), 214 I/O162 5A2 (io), 215 I/O163 5A3 (io), 216 I/O164 5A4 (io), 217 I/O165 5A5 (io), 218 I/O166 5A6 (io), 219 I/O167 5A7 (io), 221 I/O168 5A8 (io), 222 I/O169 5A9 (io), 223 I/O170 5A10 (io), 224 I/O171 5A11 (io), 225 I/O172 5A12 (io), 226 I/O173 5A13 (io), 227 I/O174 5A14 (io), 228 I/O175 5A15 (io), 231 I/O176 0B13 (io), 232 I/O177 0B12 (io), 233 I/O178 0B11 (io), 234 I/O179 0B8 (io), 235 I/O180 0B7 (io), 236 I/O181 0B4 (io), 237 I/O182 0B3 (io), 238 I/O183 0B2 (io)
part B pins: 1 TDI (in), 10 VCC (power), 11 GND (power), 20 GND (power), 29 I0/CLK0 (in), 30 VCC (power), 31 GND (power), 32 I1/CLK1 (in), 41 GND (power), 50 GND (power), 51 VCC (power), 60 TCK (in), 61 GND (power), 62 VCC (power), 71 GND (power), 72 VCC (power), 81 GND (power), 88 VCC (power), 89 GND (power), 90 GND (power), 91 GND (power), 92 GND (power), 93 VCC (power), 100 GND (power), 109 VCC (power), 110 GND (power), 119 VCC (power), 120 GND (power), 121 TMS (in), 130 VCC (power), 131 GND (power), 140 GND (power), 149 I2/CLK2 (in), 150 VCC (power), 151 GND (power), 152 I3/CLK3 (in), 161 GND (power), 170 GND (power), 171 VCC (power), 180 TDO (out), 181 GND (power), 182 VCC (power), 191 GND (power), 192 VCC (power), 201 GND (power), 208 VCC (power), 209 GND (power), 210 GND (power), 211 GND (power), 212 GND (power), 213 VCC (power), 220 GND (power), 229 VCC (power), 230 GND (power), 239 VCC (power), 240 GND (power)

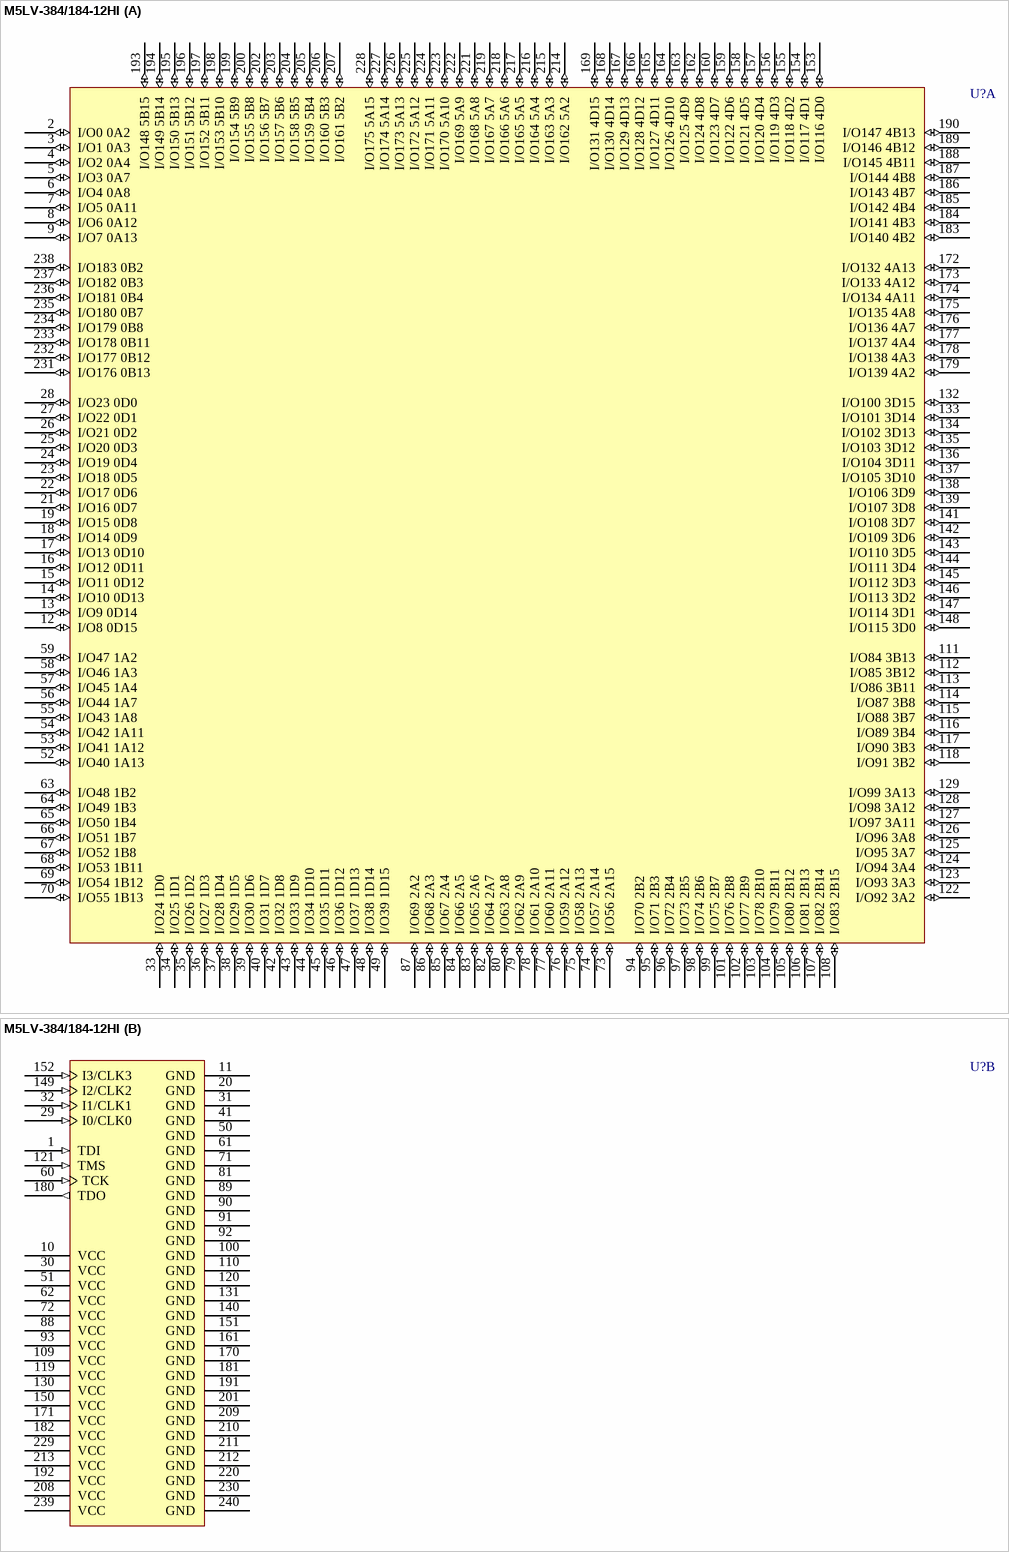
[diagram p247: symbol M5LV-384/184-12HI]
